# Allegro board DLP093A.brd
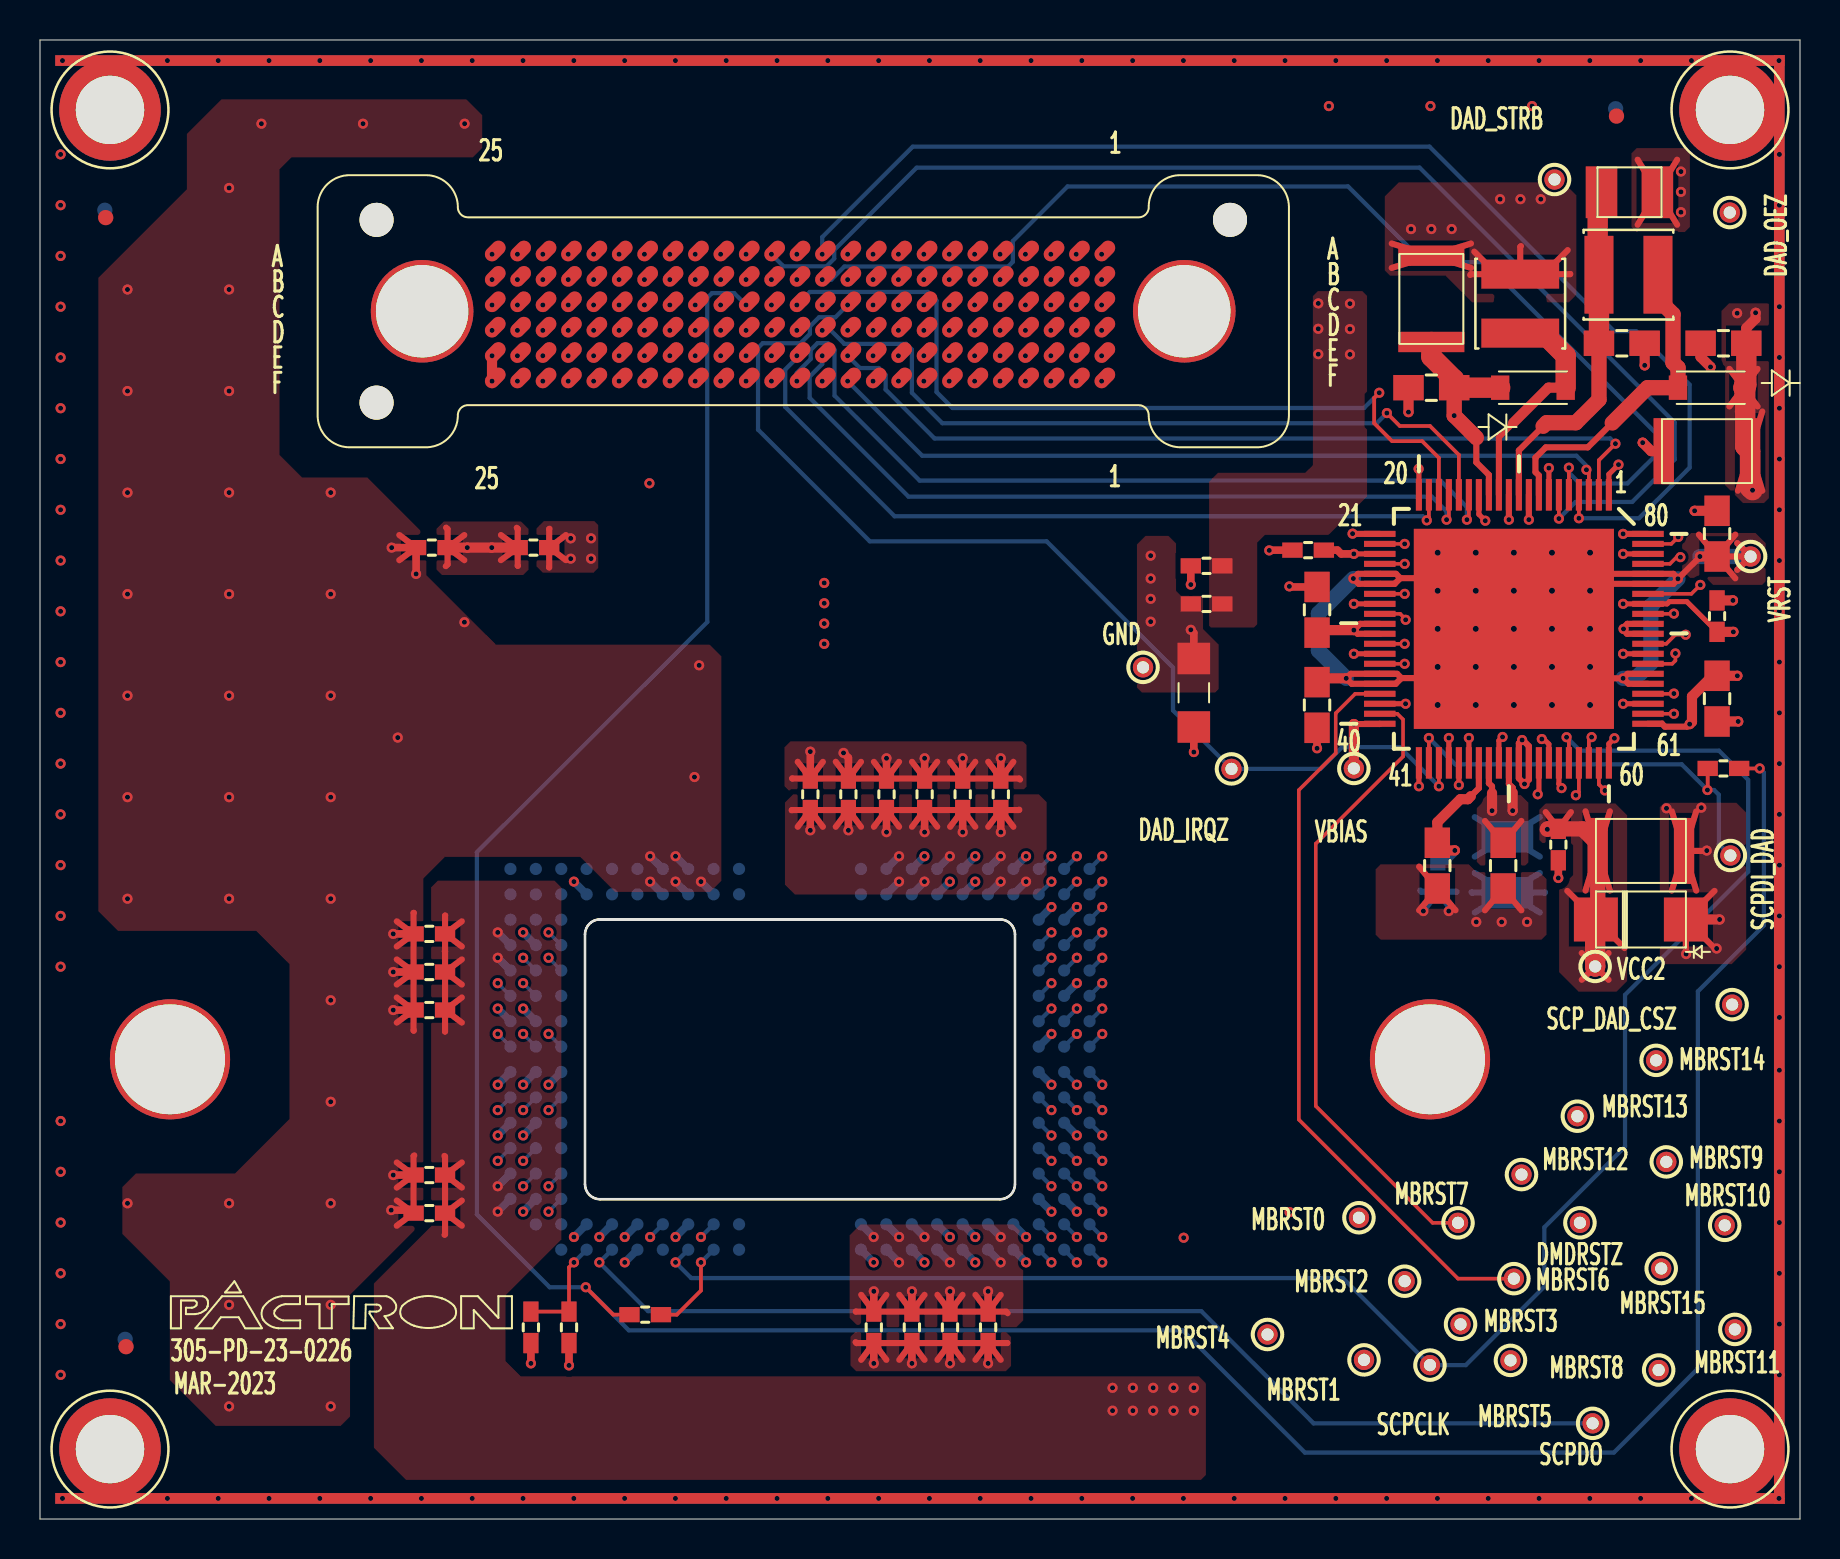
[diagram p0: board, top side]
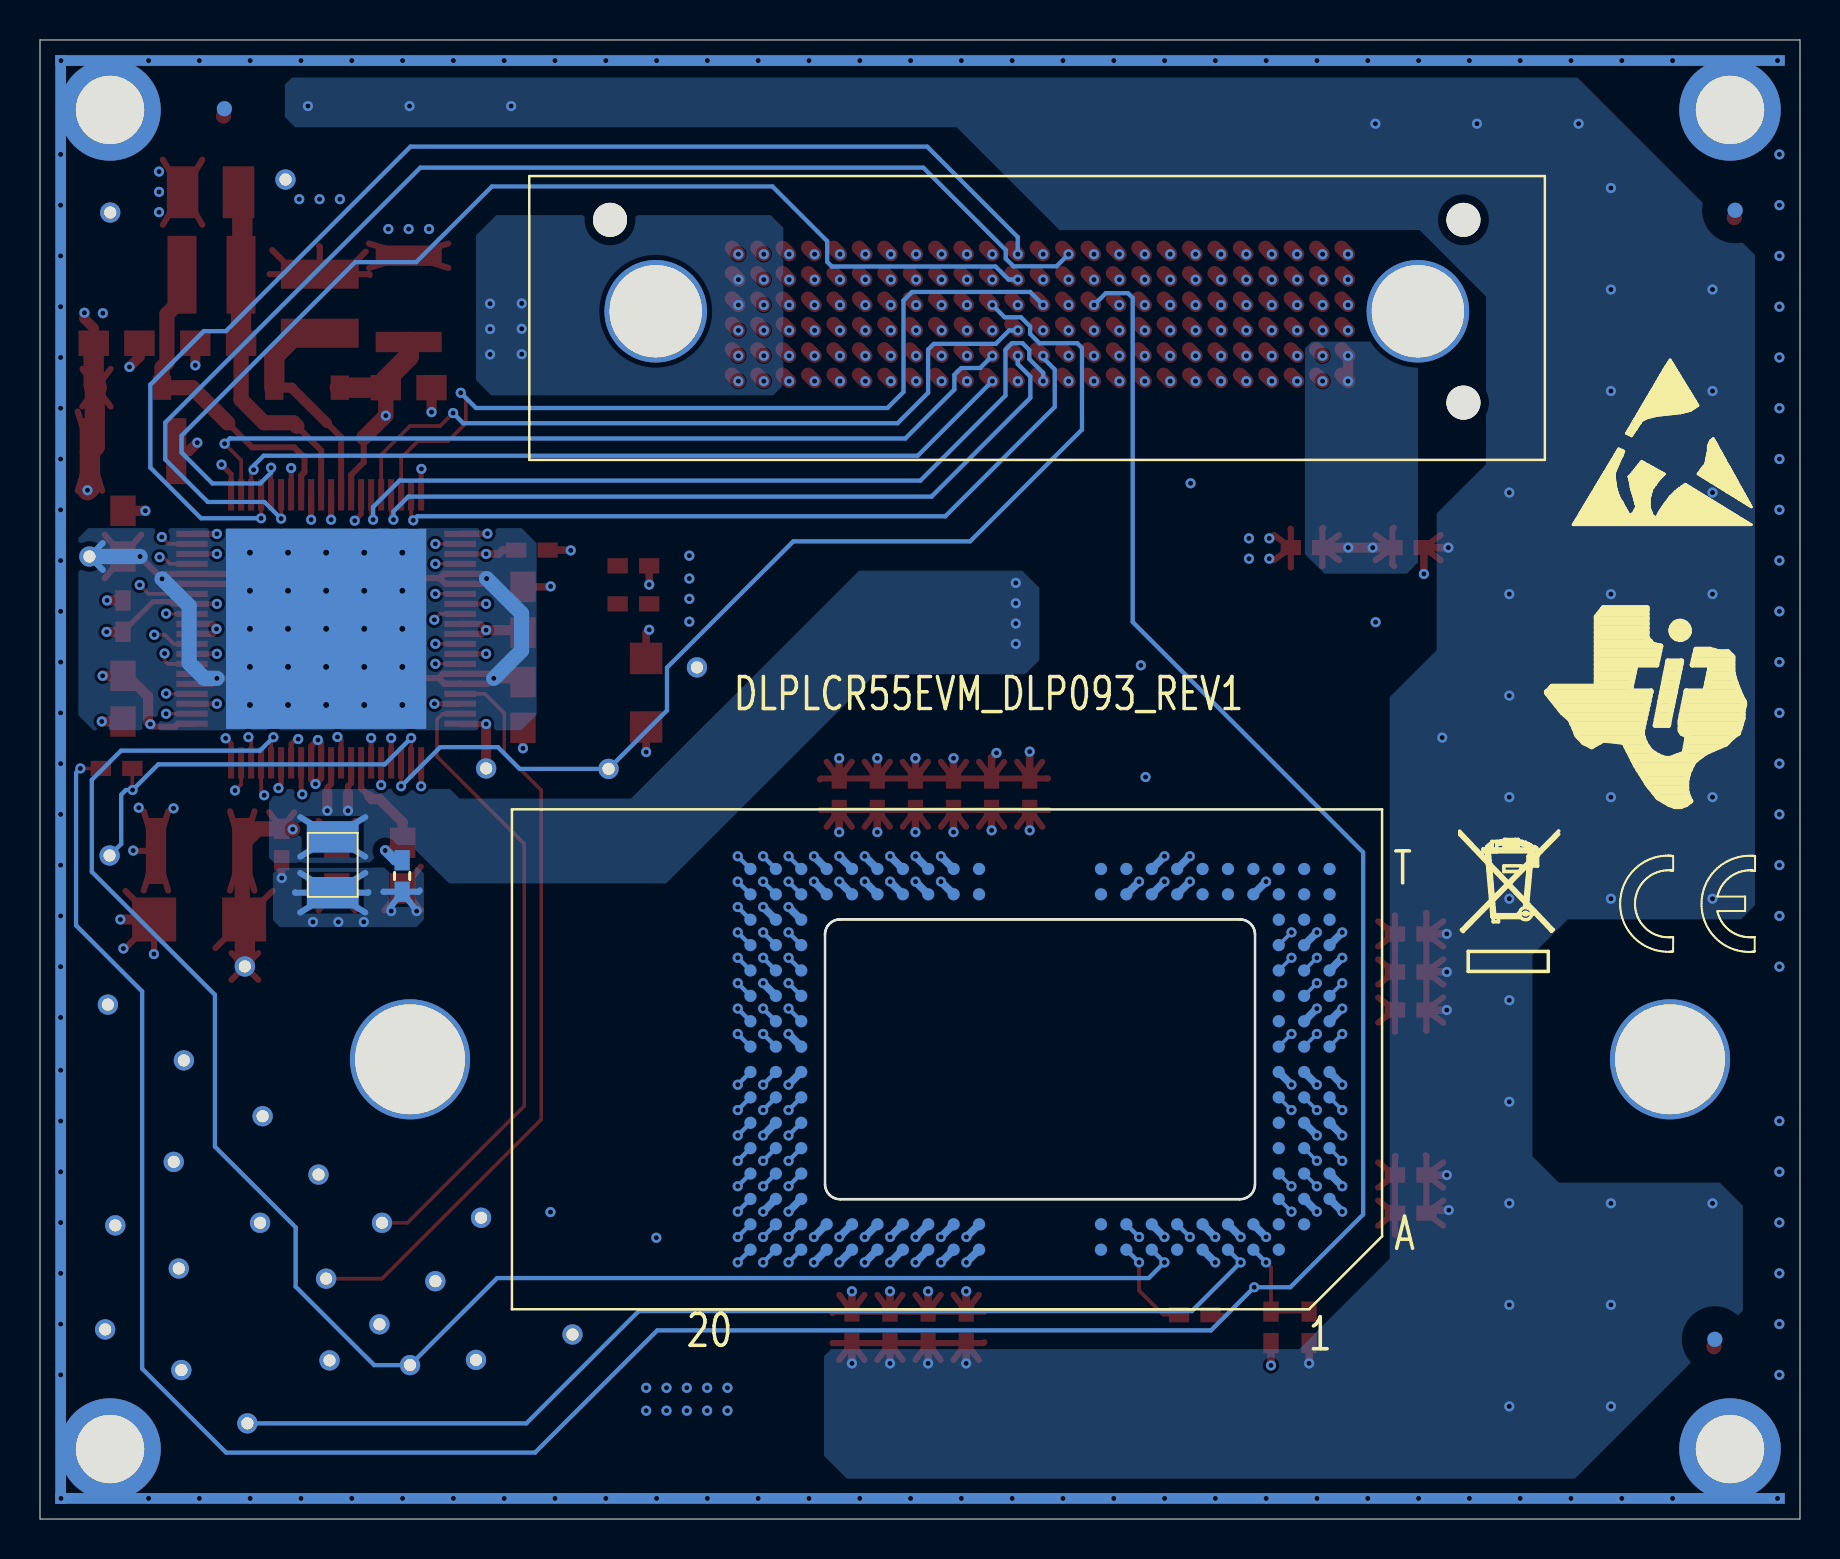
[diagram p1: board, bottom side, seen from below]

Outline 88 x 74 mm; copper layers: TOP, 02_PWR, 03_GND1, 04_SIG1, 05_GND2, 06_SIG2, 07_GND3, BOTTOM. Coordinates in mm from the lower left corner of the outline.
Outline path: 27.25,29.25 arc(27.47,29.78) 28,30 48,30 arc(48.53,29.78) 48.75,29.25 48.75,16.75 arc(48.53,16.22) 48,16 28,16 arc(27.47,16.22) 27.25,16.75 27.25,29.25

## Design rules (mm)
net group C: nets DMDRSTZ SCPCLK SCPDI SCPDO
net group DIFF: nets DCLKAN DCLKAP DCLKBN DCLKBP DDAN5 DDAN9 DDAN11 DDAN13 DDAN15 DDAP5 DDAP9 DDAP11 DDAP13 DDAP15 DDBN3 DDBN5 DDBN7 DDBN9 DDBN13 DDBN15 DDBP3 DDBP5 DDBP7 DDBP9 DDBP13 DDBP15 SCTRLAN SCTRLAP SCTRLBN SCTRLBP
net group MBRST: nets MBRST0 MBRST1 MBRST2 MBRST3 MBRST4 MBRST5 MBRST6 MBRST7 MBRST8 MBRST9 MBRST10 MBRST11 MBRST12 MBRST13 MBRST14 MBRST15
net group POWER_PH: nets DAD_VBIAS_SWL V5REG VBIAS_LHI VRST_SWL

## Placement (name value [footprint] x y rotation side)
C1  0.001uF  [0603AVX]  19.59 48.6 180 top
C2  0.001uF  [0603AVX]  58.33 47.69 180 top
C3  0.1uF  [0603AVX]  38.52 36.26 90 top
C4  0.1uF  [0603AVX]  40.42 36.26 90 top
C5  0.1uF  [0603AVX]  42.33 36.26 90 top
C6  0.1uF  [0603AVX]  44.23 36.26 90 top
C7  0.1uF  [0603AVX]  46.14 36.26 90 top
C8  0.1uF  [0603AVX]  48.04 36.26 90 top
C9  10uF  [1206AVX]  57.69 41.34 270 top
C10  10 uF  [CAP_1210]  79.47 66.38 0 top
C11  0.1uF  [0603AVX]  19.47 29.28 180 top
C12  1uF  [0603AVX]  19.47 27.37 180 top
C13  0.1uF  [0603AVX]  19.47 25.47 180 top
C14  0.1uF  [0603AVX]  63.41 48.48 0 top
C15  4.7 uF  [CAP_1812]  69.57 61.05 270 top
C16  0.1 uF  [CAP_0805]  69.57 56.6 0 top
C17  0.1 uF  [CAP_0805]  79.09 58.83 180 top
C18  0.1 uF  [CAP_0805]  84.17 58.83 0 top
C19  4.7 uF  [CAP_1812]  83.35 53.43 0 top
C20  0.1 uF  [CAP_0805]  83.85 49.3 270 top
C21  0.1uF  [0603AVX]  19.47 17.21 180 top
C22  0.1uF  [0603AVX]  19.47 15.31 180 top
C23  0.1uF  [0603AVX]  41.69 9.59 270 top
C24  0.1uF  [0603AVX]  43.6 9.59 270 top
C25  0.1uF  [0603AVX]  45.5 9.59 270 top
C26  0.1uF  [0603AVX]  47.41 9.59 270 top
C27  0.1 uF  [CAP_0805]  63.85 45.49 270 top
C28  0.1 uF  [CAP_0805]  63.85 40.73 90 top
C29  0.1uF  [0603AVX]  83.85 45.17 270 top
C30  0.1 uF  [CAP_0805]  83.85 41.05 90 top
C31  1uF  [0603AVX]  69.89 32.17 270 bottom
C32  10 uF  [CAP_1210]  73.36 32.73 270 bottom
C33  0.1 uF  [CAP_0805]  69.87 32.69 90 top
C34  0.1 uF  [CAP_0805]  73.16 32.69 90 top
C35  0.1uF  [0603AVX]  75.92 33.74 90 top
C36  4.7 uF  [CAP_1812]  80.04 33.43 180 top
D1  DIODE_SCHOTTKY  [SOD_123]  74.65 56.6 180 top
D2  DIODE_SCHOTTKY  [SOD_123]  83.54 56.6 180 top
D3  9.1V  [DO-214AC]  80.04 30 180 top
J1  DMD_FLEX_CONNECTOR  [CN150CUSTOM_REVB]  53.4 63.6 180 top
L1  68ohms @ 100MHz  [0603AVX]  24.67 48.6 0 top
L2  68ohms @ 100MHz  [0603AVX]  58.33 45.79 0 top
L3  22 uH  [IND_DT1608C]  74.01 60.81 270 top
L4  22 uH  [IND_DT1608C]  79.42 62.25 0 top
MH1  Mounting_Hole  [MOUNTING_HOLE]  3.5 3.5 0 top
MH2  Mounting_Hole  [MOUNTING_HOLE]  84.5 70.5 0 top
MH3  Mounting_Hole  [MOUNTING_HOLE]  3.5 70.5 0 top
MH4  Mounting_Hole  [MOUNTING_HOLE]  84.5 3.5 0 top
NOREF  -  []  28 16 90 top
NOREF#2  -  []  27.25 16.75 0 top
NOREF#3  -  [unnamed#2]  3.29 65.11 0 top
NOREF#4  -  []  -87.55 -119.7 0 top
NOREF#5  -  []  -35.47 -36.19 90 top
NOREF#6  -  []  0 74 0 top
NOREF#7  -  []  119.08 -36.19 90 top
NOREF#8  -  []  -35.47 95.16 90 top
NOREF#9  -  []  0 0 90 top
NOREF#10  -  []  67.48 41.03 0 top
NOREF#11  -  []  -125.33 -140.66 0 top
NOREF#12  -  [unnamed#2]  4.3 8.62 0 top
NOREF#13  -  [unnamed#2]  78.82 70.19 0 top
NOREF#14  -  []  48.62 29.67 0 top
NOREF#15  -  []  19.48 5.03 0 top
NOREF#16  -  []  67.48 5.03 180 bottom
NOREF#17  -  [unnamed#2]  78.78 70.56 180 bottom
NOREF#18  -  [unnamed#2]  3.24 65.48 180 bottom
NOREF#19  -  [unnamed#2]  4.26 8.99 180 bottom
NOREF#20  -  []  21.37 42.13 180 bottom
NOREF#21  -  []  19.48 41.03 180 bottom
NOREF#22  -  [unnamed#3]  38 23 180 bottom
NOREF#23  -  []  45.5 43.4 180 bottom
R1  0  [0603AVX]  24.55 9.59 90 top
R2  0  [0603AVX]  26.45 9.59 270 top
R3  33  [0603AVX]  30.26 10.23 0 top
R4  33  [0603AVX]  84.17 37.55 180 top
TP1  Testpoint  [TP40_24]  55.15 42.61 0 top
TP2  Testpoint  [TP40_24]  65.95 15.07 0 top
TP3  Testpoint  [TP40_24]  66.2 7.96 0 top
TP4  Testpoint  [TP40_24]  68.23 11.9 0 top
TP5  Testpoint  [TP40_24]  71.03 9.74 0 top
TP6  Testpoint  [TP40_24]  61.38 9.23 0 top
TP7  Testpoint  [TP40_24]  73.52 7.94 0 top
TP8  Testpoint  [TP40_24]  73.69 12.03 0 top
TP9  Testpoint  [TP40_24]  70.9 14.82 0 top
TP10  Testpoint  [TP40_24]  80.93 7.45 0 top
TP11  Testpoint  [TP40_24]  81.31 17.87 0 top
TP12  Testpoint  [TP40_24]  84.24 14.69 0 top
TP13  Testpoint  [TP40_24]  84.74 9.49 0 top
TP14  Testpoint  [TP40_24]  74.08 17.23 0 top
TP15  Testpoint  [TP40_24]  76.87 20.15 0 top
TP16  Testpoint  [TP40_24]  80.81 22.95 0 top
TP17  Testpoint  [TP40_24]  81.06 12.53 0 top
TP18  Testpoint  [TP40_24]  69.5 7.7 0 top
TP19  Testpoint  [TP40_24]  77.63 4.79 0 top
TP20  Testpoint  [TP40_24]  84.52 33.2 0 top
TP21  Testpoint  [TP40_24]  84.61 25.74 0 top
TP22  Testpoint  [TP40_24]  59.57 37.53 0 top
TP23  Testpoint  [TP40_24]  75.73 67.02 0 top
TP24  Testpoint  [TP40_24]  84.49 65.37 0 top
TP25  Testpoint  [TP40_24]  77 14.82 0 top
TP26  Testpoint  [TP40_24]  65.69 37.55 0 top
TP27  Testpoint  [TP40_24]  85.53 48.16 0 top
TP28  Testpoint  [TP40_24]  77.76 27.65 0 top
U1  DAD2000  [TQFP80_5MM]  73.69 44.54 180 top
U500  Series 450 DMD  [DMD_S450]  38 23 0 bottom

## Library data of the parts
C1-C9 C11-C31 C33-C36 = CAP NP
C10 C32 = CAP NP: Tolerance: TOL
D1 D2 = DIODE_SCHOTTKY
D3 = DIODE ZENER
J1 = DMD_FLEX_CONNECTOR_1
L1-L4 = INDUCTOR
MH1-MH4 TP1-TP28 = Testpoint
R1-R4 = R
U1 = DAD2000
U500 = Series 450 DMD

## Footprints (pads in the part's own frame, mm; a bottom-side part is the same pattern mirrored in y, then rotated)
0603AVX
  rect 1.016x0.762 smd: 1(-0.787,0) 2(0.787,0)
1206AVX
  rect 1.575x1.626 smd: 1(-1.715,0) 2(1.715,0)
CAP_0805
  rect 1.524x1.27 smd: 1(-1.143,0) 2(1.143,0)
CAP_1210
  rect 1.575x2.591 smd: 1(-1.397,0) 2(1.397,0)
CAP_1812
  rect 1.016x3.302 smd: 1(-2.158,0) 2(2.158,0)
CN150CUSTOM_REVB
  round 1.7 hole 1.7 unplated: (-6.096,-1.397) (36.576,7.747) (36.576,-1.397)
  oval 1.168x0.711 smd rot 45: 1A(0,0) 1B(0,1.27) 1C(0,2.54) 1D(0,3.81) 1E(0,5.08) 1F(0,6.35) 2A(1.27,0) 2B(1.27,1.27) 2C(1.27,2.54) 2D(1.27,3.81) 2E(1.27,5.08) 2F(1.27,6.35) 3A(2.54,0) 3B(2.54,1.27) 3C(2.54,2.54) 3D(2.54,3.81) 3E(2.54,5.08) 3F(2.54,6.35) 4A(3.81,0) 4B(3.81,1.27) 4C(3.81,2.54) 4D(3.81,3.81) 4E(3.81,5.08) 4F(3.81,6.35) 5A(5.08,0) 5B(5.08,1.27) 5C(5.08,2.54) 5D(5.08,3.81) 5E(5.08,5.08) 5F(5.08,6.35) 6A(6.35,0) 6B(6.35,1.27) 6C(6.35,2.54) 6D(6.35,3.81) 6E(6.35,5.08) 6F(6.35,6.35) 7A(7.62,0) 7B(7.62,1.27) 7C(7.62,2.54) 7D(7.62,3.81) 7E(7.62,5.08) 7F(7.62,6.35) 8A(8.89,0) 8B(8.89,1.27) 8C(8.89,2.54) 8D(8.89,3.81) 8E(8.89,5.08) 8F(8.89,6.35) 9A(10.16,0) 9B(10.16,1.27) 9C(10.16,2.54) 9D(10.16,3.81) 9E(10.16,5.08) 9F(10.16,6.35) 10A(11.43,0) 10B(11.43,1.27) 10C(11.43,2.54) 10D(11.43,3.81) 10E(11.43,5.08) 10F(11.43,6.35) 11A(12.7,0) 11B(12.7,1.27) 11C(12.7,2.54) 11D(12.7,3.81) 11E(12.7,5.08) 11F(12.7,6.35) 12A(13.97,0) 12B(13.97,1.27) 12C(13.97,2.54) 12D(13.97,3.81) 12E(13.97,5.08) 12F(13.97,6.35) 13A(15.24,0) 13B(15.24,1.27) 13C(15.24,2.54) 13D(15.24,3.81) 13E(15.24,5.08) 13F(15.24,6.35) 14A(16.51,0) 14B(16.51,1.27) 14C(16.51,2.54) 14D(16.51,3.81) 14E(16.51,5.08) 14F(16.51,6.35) 15A(17.78,0) 15B(17.78,1.27) 15C(17.78,2.54) 15D(17.78,3.81) 15E(17.78,5.08) 15F(17.78,6.35) 16A(19.05,0) 16B(19.05,1.27) 16C(19.05,2.54) 16D(19.05,3.81) 16E(19.05,5.08) 16F(19.05,6.35) 17A(20.32,0) 17B(20.32,1.27) 17C(20.32,2.54) 17D(20.32,3.81) 17E(20.32,5.08) 17F(20.32,6.35) 18A(21.59,0) 18B(21.59,1.27) 18C(21.59,2.54) 18D(21.59,3.81) 18E(21.59,5.08) 18F(21.59,6.35) 19A(22.86,0) 19B(22.86,1.27) 19C(22.86,2.54) 19D(22.86,3.81) 19E(22.86,5.08) 19F(22.86,6.35) 20A(24.13,0) 20B(24.13,1.27) 20C(24.13,2.54) 20D(24.13,3.81) 20E(24.13,5.08) 20F(24.13,6.35) 21A(25.4,0) 21B(25.4,1.27) 21C(25.4,2.54) 21D(25.4,3.81) 21E(25.4,5.08) 21F(25.4,6.35) 22A(26.67,0) 22B(26.67,1.27) 22C(26.67,2.54) 22D(26.67,3.81) 22E(26.67,5.08) 22F(26.67,6.35) 23A(27.94,0) 23B(27.94,1.27) 23C(27.94,2.54) 23D(27.94,3.81) 23E(27.94,5.08) 23F(27.94,6.35) 24A(29.21,0) 24B(29.21,1.27) 24C(29.21,2.54) 24D(29.21,3.81) 24E(29.21,5.08) 24F(29.21,6.35) 25A(30.48,0) 25B(30.48,1.27) 25C(30.48,2.54) 25D(30.48,3.81) 25E(30.48,5.08) 25F(30.48,6.35)
  round 5.131 hole 4.623: MH1(-3.809,3.176) MH2(34.298,3.176)
DMD_S450
  round 0.61 smd: A3(-11.938,9.525) A4(-10.668,9.525) A5(-9.398,9.525) A6(-8.128,9.525) A7(-6.858,9.525) A8(-5.588,9.525) A9(-4.318,9.525) A10(-3.048,9.525) A11(3.048,9.525) A12(4.318,9.525) A13(5.588,9.525) A14(6.858,9.525) A15(8.128,9.525) A16(9.398,9.525) A17(10.668,9.525) A18(11.938,9.525) A19(13.208,9.525) A20(14.478,9.525) B2(-13.208,8.255) B3(-11.938,8.255) B4(-10.668,8.255) B5(-9.398,8.255) B6(-8.128,8.255) B7(-6.858,8.255) B8(-5.588,8.255) B9(-4.318,8.255) B10(-3.048,8.255) B11(3.048,8.255) B12(4.318,8.255) B13(5.588,8.255) B14(6.858,8.255) B15(8.128,8.255) B16(9.398,8.255) B17(10.668,8.255) B18(11.938,8.255) B19(13.208,8.255) B20(14.478,8.255) C1(-14.478,6.985) C2(-13.208,6.985) C3(-11.938,6.985) C18(11.938,6.985) C19(13.208,6.985) C20(14.478,6.985) D1(-14.478,5.715) D2(-13.208,5.715) D3(-11.938,5.715) D18(11.938,5.715) D19(13.208,5.715) D20(14.478,5.715) E1(-14.478,4.445) E2(-13.208,4.445) E3(-11.938,4.445) E18(11.938,4.445) E19(13.208,4.445) E20(14.478,4.445) F1(-14.478,3.175) F2(-13.208,3.175) F3(-11.938,3.175) F18(11.938,3.175) F19(13.208,3.175) F20(14.478,3.175) G1(-14.478,1.905) G2(-13.208,1.905) G3(-11.938,1.905) G18(11.938,1.905) G19(13.208,1.905) G20(14.478,1.905) H1(-14.478,0.635) H2(-13.208,0.635) H3(-11.938,0.635) H18(11.938,0.635) H19(13.208,0.635) H20(14.478,0.635) J1(-14.478,-0.635) J2(-13.208,-0.635) J3(-11.938,-0.635) J18(11.938,-0.635) J19(13.208,-0.635) J20(14.478,-0.635) K1(-14.478,-1.905) K2(-13.208,-1.905) K3(-11.938,-1.905) K18(11.938,-1.905) K19(13.208,-1.905) K20(14.478,-1.905) L1(-14.478,-3.175) L2(-13.208,-3.175) L3(-11.938,-3.175) L18(11.938,-3.175) L19(13.208,-3.175) L20(14.478,-3.175) M1(-14.478,-4.445) M2(-13.208,-4.445) M3(-11.938,-4.445) M18(11.938,-4.445) M19(13.208,-4.445) M20(14.478,-4.445) N1(-14.478,-5.715) N2(-13.208,-5.715) N3(-11.938,-5.715) N18(11.938,-5.715) N19(13.208,-5.715) N20(14.478,-5.715) P1(-14.478,-6.985) P2(-13.208,-6.985) P3(-11.938,-6.985) P18(11.938,-6.985) P19(13.208,-6.985) P20(14.478,-6.985) R1(-14.478,-8.255) R2(-13.208,-8.255) R3(-11.938,-8.255) R4(-10.668,-8.255) R5(-9.398,-8.255) R6(-8.128,-8.255) R7(-6.858,-8.255) R8(-5.588,-8.255) R9(-4.318,-8.255) R10(-3.048,-8.255) R11(3.048,-8.255) R12(4.318,-8.255) R13(5.588,-8.255) R14(6.858,-8.255) R15(8.128,-8.255) R16(9.398,-8.255) R17(10.668,-8.255) R18(11.938,-8.255) R19(13.208,-8.255) R20(14.478,-8.255) T1(-14.478,-9.525) T2(-13.208,-9.525) T3(-11.938,-9.525) T4(-10.668,-9.525) T5(-9.398,-9.525) T6(-8.128,-9.525) T7(-6.858,-9.525) T8(-5.588,-9.525) T9(-4.318,-9.525) T10(-3.048,-9.525) T11(3.048,-9.525) T12(4.318,-9.525) T13(5.588,-9.525) T14(6.858,-9.525) T15(8.128,-9.525) T16(9.398,-9.525) T17(10.668,-9.525) T18(11.938,-9.525) T19(13.208,-9.525) T20(14.478,-9.525)
DO-214AC
  rect 2.2x2.2 smd: 1(2.25,0) 2(-2.25,0)
IND_DT1608C
  rect 1.45x3.89 smd: 1(-1.475,0) 2(1.475,0)
MOUNTING_HOLE
  round 5.08 hole 3.42: 1(0,0)
SOD_123
  rect 0.914x1.219 smd: 1(-1.638,0) 2(1.638,0)
TP40_24
  round 1.016 hole 0.61: 1(0,0)
TQFP80_5MM
  rect 0.305x1.575 smd: 1(-4.75,-6.706) 2(-4.249,-6.706) 3(-3.749,-6.706) 4(-3.251,-6.706) 5(-2.751,-6.706) 6(-2.25,-6.706) 7(-1.75,-6.706) 8(-1.25,-6.706) 9(-0.749,-6.706) 10(-0.249,-6.706) 11(0.249,-6.706) 12(0.749,-6.706) 13(1.25,-6.706) 14(1.75,-6.706) 15(2.25,-6.706) 16(2.751,-6.706) 17(3.251,-6.706) 18(3.749,-6.706) 19(4.249,-6.706) 20(4.75,-6.706) 41(4.75,6.706) 42(4.249,6.706) 43(3.749,6.706) 44(3.251,6.706) 45(2.751,6.706) 46(2.25,6.706) 47(1.75,6.706) 48(1.25,6.706) 49(0.749,6.706) 50(0.249,6.706) 51(-0.249,6.706) 52(-0.749,6.706) 53(-1.25,6.706) 54(-1.75,6.706) 55(-2.25,6.706) 56(-2.751,6.706) 57(-3.251,6.706) 58(-3.749,6.706) 59(-4.249,6.706) 60(-4.75,6.706)
  rect 1.575x0.305 smd: 21(6.706,-4.75) 22(6.706,-4.249) 23(6.706,-3.749) 24(6.706,-3.251) 25(6.706,-2.751) 26(6.706,-2.25) 27(6.706,-1.75) 28(6.706,-1.25) 29(6.706,-0.749) 30(6.706,-0.249) 31(6.706,0.249) 32(6.706,0.749) 33(6.706,1.25) 34(6.706,1.75) 35(6.706,2.25) 36(6.706,2.751) 37(6.706,3.251) 38(6.706,3.749) 39(6.706,4.249) 40(6.706,4.75) 61(-6.706,4.75) 62(-6.706,4.249) 63(-6.706,3.749) 64(-6.706,3.251) 65(-6.706,2.751) 66(-6.706,2.25) 67(-6.706,1.75) 68(-6.706,1.25) 69(-6.706,0.749) 70(-6.706,0.249) 71(-6.706,-0.249) 72(-6.706,-0.749) 73(-6.706,-1.25) 74(-6.706,-1.75) 75(-6.706,-2.25) 76(-6.706,-2.751) 77(-6.706,-3.251) 78(-6.706,-3.749) 79(-6.706,-4.249) 80(-6.706,-4.75)
unnamed#2
  round 0.762 smd: (0,0)
unnamed#3
  round 6.008 hole 5.5 unplated: (-31.5,0) (31.5,0)

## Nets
GND: C1.2 C2.2 C3.2 C4.2 C5.2 C6.2 C7.2 C8.2 C9.2 C10.2 C11.2 C12.2 C13.2 C14.1 C15.1 C16.1 C17.1 C18.1 C19.1 C20.1 C21.2 C22.2 C23.2 C24.2 C25.2 C26.2 C27.1 C28.1 C29.1 C30.1 C31.2 C32.2 C33.1 C34.1 C35.1 C36.1 D3.2(ANODE) J1.1A J1.1D J1.2C J1.2F J1.3A J1.3D J1.4C J1.4F J1.5A J1.5D J1.6C J1.6F J1.7A J1.7D J1.8C J1.8F J1.9A J1.9D J1.10C J1.10F J1.11A J1.11D J1.12C J1.12F J1.13D J1.14C J1.14F J1.15A J1.15D J1.16C J1.16F J1.17A J1.17D J1.18C J1.18F J1.19A J1.19D J1.20C J1.20F J1.21A J1.21D J1.22C J1.22F J1.23A J1.23D J1.24C J1.24F J1.25A J1.25D J1.MH1 J1.MH2 L3.1 MH1.1 MH2.1 MH3.1 MH4.1 R1.1 TP1.1 U1.1(GND_1) U1.7(GND_7) U1.14(GND_14) U1.20(GND_20) U1.41(GND_41) U1.44(DEV_ID0) U1.45(DEV_ID1) U1.46(GND_46) U1.53(GND_53) U1.54(VCC/NC) U1.55(GND_55) U1.60(GND_60) U500.A6(GND#A6) U500.A11(GND#A11) U500.A13(GND#A13) U500.A15(GND#A15) U500.A17(GND#A17) U500.B4(GND#B4) U500.B5(GND#B5) U500.B6(RESERVED_STM) U500.B8(GND#B8) U500.B14(GND#B14) U500.B15(GND#B15) U500.B17(GND#B17) U500.C2(GND#C2) U500.C18(GND#C18) U500.C19(GND#C19) U500.F1(GND#F1) U500.F2(GND#F2) U500.F19(GND#F19) U500.H1(GND#H1) U500.H2(GND#H2) U500.H3(GND#H3) U500.H18(GND#H18) U500.J18(GND#J18) U500.K1(GND#K1) U500.K2(GND#K2) U500.L19(GND#L19) U500.N2(GND#N2) U500.P18(GND#P18) U500.P19(GND#P19) U500.R4(GND#R4) U500.R7(RESERVED_FC) U500.R8(RESERVED_FD) U500.R9(GND#R9) U500.R14(GND#R14) U500.R15(GND#R15) U500.T7(GND#T7) U500.T8(RESERVED_PFE) U500.T13(GND#T13) U500.T15(GND#T15) U500.T17(GND#T17)
P12V: C32.1 C34.2 J1.10D J1.10E J1.11B U1.11(V12_1) U1.48(V12_2) U1.50(V12_3)
V5REG: C31.1 C33.2 U1.47(V5REG)
V12_SWL-NC: U1.51(V12_SWL-NC#51) U1.52(V12_SWL-NC#52)
VCC: C3.1 C4.1 C5.1 C6.1 C7.1 C8.1 C9.1 C23.1 C24.1 C25.1 C26.1 L1.2 L2.1 R2.2 U500.A12(VCCI#A12) U500.A14(VCCI#A14) U500.A16(VCCI#A16) U500.B11(VCC#B11) U500.B12(VCC#B12) U500.B13(VCC#B13) U500.B16(VCC#B16) U500.R12(VCC#R12) U500.R13(VCC#R13) U500.R16(VCC#R16) U500.R17(VCC#R17) U500.T12(VCCI#T12) U500.T14(VCCI#T14) U500.T16(VCCI#T16)
VCC2: C11.1 C12.1 C13.1 C14.2 C21.1 C22.1 C29.2 C35.2 C36.2 D3.1(CATHODE) TP28.1 U1.23(VOFFSET_RAIL0) U1.28(VOFFSET_RAIL1) U1.33(VOFFSET_RAIL2) U1.38(VOFFSET_RAIL3) U1.49(VOFFSET) U1.63(VOFFSET_RAIL4) U1.68(VOFFSET_RAIL5) U1.73(VOFFSET_RAIL6) U1.78(VOFFSET_RAIL7) U500.C1(VCC2#C1) U500.D1(VCC2#D1) U500.M1(VCC2#M1) U500.N1(VCC2#N1)
3P3V: C2.1 J1.1B J1.1C L2.2
13A: J1.13A
13B: J1.13B
DAD_ADDR_0: J1.13E U1.19(A0)
DAD_ADDR_1: J1.13C U1.18(A1)
DAD_ADDR_2: J1.12E U1.17(A2)
DAD_ADDR_3: J1.12D U1.16(A3)
DAD_IRQZ: J1.11C TP22.1 U1.43(IRQZ)
DAD_MODE_0: J1.11F U1.3(MODE0)
DAD_MODE_1: J1.11E U1.2(MODE1)
DAD_OEZ: J1.14A TP24.1 U1.6(OEZ)
DAD_SEL_0: J1.12B U1.5(SEL0)
DAD_SEL_1: J1.12A U1.4(SEL1)
DAD_STRB: J1.13F TP23.1 U1.15(STROBE)
DAD_VBIAS_SWL: D2.2(A) L4.2 U1.8(VBIAS_SWL)
DCLKAN: J1.21E U500.D19(DCLKA-)
DCLKAP: J1.21F U500.E19(DCLKA+)
DCLKBN: J1.5E U500.N19(DCLKB-)
DCLKBP: J1.5F U500.M19(DCLKB+)
DDAN1: J1.17E U500.G20(DDA1-)
DDAN3: J1.18D U500.H19(DDA3-)
DDAN5: J1.19E U500.F18(DDA5-)
DDAN7: J1.20D U500.E18(DDA7-)
DDAN9: J1.22D U500.C20(DDA9-)
DDAN11: J1.23E U500.B18(DDA11-)
DDAN13: J1.24D U500.A20(DDA13-)
DDAN15: J1.25B U500.B19(DDA15-)
DDAP1: J1.17F U500.H20(DDA1+)
DDAP3: J1.18E U500.G19(DDA3+)
DDAP5: J1.19F U500.G18(DDA5+)
DDAP7: J1.20E U500.D18(DDA7+)
DDAP9: J1.22E U500.D20(DDA9+)
DDAP11: J1.23F U500.A18(DDA11+)
DDAP13: J1.24E U500.B20(DDA13+)
DDAP15: J1.25C U500.A19(DDA15+)
DDBN1: J1.9E U500.K20(DDB1-)
DDBN3: J1.8D U500.J19(DDB3-)
DDBN5: J1.7E U500.L18(DDB5-)
DDBN7: J1.6D U500.M18(DDB7-)
DDBN9: J1.4D U500.P20(DDB9-)
DDBN11: J1.3E U500.R18(DDB11-)
DDBN13: J1.2D U500.T20(DDB13-)
DDBN15: J1.1E U500.R19(DDB15-)
DDBP1: J1.9F U500.J20(DDB1+)
DDBP3: J1.8E U500.K19(DDB3+)
DDBP5: J1.7F U500.K18(DDB5+)
DDBP7: J1.6E U500.N18(DDB7+)
DDBP9: J1.4E U500.N20(DDB9+)
DDBP11: J1.3F U500.T18(DDB11+)
DDBP13: J1.2E U500.R20(DDB13+)
DDBP15: J1.1F U500.T19(DDB15+)
DMDRSTZ: J1.15B TP25.1 U1.59(RESETZ) U500.B9(PWRDNZ)
MBRST0: TP2.1 U1.22(OUT00) U500.C3(MBRST00)
MBRST1: TP3.1 U1.24(OUT01) U500.D2(MBRST01)
MBRST2: TP4.1 U1.27(OUT02) U500.D3(MBRST02)
MBRST3: TP5.1 U1.29(OUT03) U500.E2(MBRST03)
MBRST4: TP6.1 U1.32(OUT04) U500.G3(MBRST04)
MBRST5: TP7.1 U1.34(OUT05) U500.E1(MBRST05)
MBRST6: TP8.1 U1.37(OUT06) U500.G2(MBRST06)
MBRST7: TP9.1 U1.39(OUT07) U500.G1(MBRST07)
MBRST8: TP10.1 U1.62(OUT08) U500.N3(MBRST08)
MBRST9: TP11.1 U1.64(OUT09) U500.M2(MBRST09)
MBRST10: TP12.1 U1.67(OUT10) U500.M3(MBRST10)
MBRST11: TP13.1 U1.69(OUT11) U500.L2(MBRST11)
MBRST12: TP14.1 U1.72(OUT12) U500.J3(MBRST12)
MBRST13: TP15.1 U1.74(OUT13) U500.L1(MBRST13)
MBRST14: TP16.1 U1.77(OUT14) U500.J2(MBRST14)
MBRST15: TP17.1 U1.79(OUT15) U500.J1(MBRST15)
MODE_A: R1.2 R2.1 U500.A4(MODE_A)
SCP_DAD_CSZ: J1.14E TP21.1 U1.58(SCPEN/)
SCPCLK: J1.16D TP18.1 U1.56(SCPCK) U500.A8(SCPCLK)
SCPDI: J1.15C R3.1 R4.1
SCPDI_DAD: R4.2 TP20.1 U1.42(SCPDO)
SCPDI_RS: R3.2 U500.A9(SCPDO)
SCPDO: J1.16E TP19.1 U1.57(SCPDI) U500.A5(SCPDI)
SCPENZ: J1.15E U500.B7(SCPENZ)
SCTRLAN: J1.20A U500.F20(SCTRLA-)
SCTRLAP: J1.20B U500.E20(SCTRLA+)
SCTRLBN: J1.6A U500.L20(SCTRLB-)
SCTRLBP: J1.6B U500.M20(SCTRLB+)
VBIAS: C18.2 C19.2 C27.2 C30.2 D2.1(C) TP26.1 U1.9(VBIAS) U1.21(VBIAS_RAIL0) U1.30(VBIAS_RAIL1) U1.31(VBIAS_RAIL2) U1.40(VBIAS_RAIL3) U1.61(VBIAS_RAIL4) U1.70(VBIAS_RAIL5) U1.71(VBIAS_RAIL6) U1.80(VBIAS_RAIL7)
VBIAS_LHI: C10.1 C17.2 L4.1 U1.10(VBIAS_LHI)
VRST: C15.2 C16.2 C20.2 C28.2 D1.2(A) TP27.1 U1.13(VRESET) U1.25(VRESET_RAIL0) U1.26(VRESET_RAIL1) U1.35(VRESET_RAIL2) U1.36(VRESET_RAIL3) U1.65(VRESET_RAIL4) U1.66(VRESET_RAIL5) U1.75(VRESET_RAIL6) U1.76(VRESET_RAIL7)
VRST_SWL: D1.1(C) L3.2 U1.12(VRESET_SWL)
N28103: C1.1 J1.25E J1.25F L1.1

Pads without a net: J1 2A 2B 3B 3C 4A 4B 5B 5C 7B 7C 8A 8B 9B 9C 10A 10B 14B 14D 15F 16A 16B 17B 17C 18A 18B 19B 19C 21B 21C 22A 22B 23B 23C 24A 24B; U500 A3 A7 A10 B2 B3 B10 E3 F3 K3 L3 P1 P2 P3 R1 R2 R3 R5 R6 R10 R11 T1 T2 T3 T4 T5 T6 T9 T10 T11

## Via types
v1: diameter 0.508, hole 0.254, TOP to BOTTOM, 598 vias
v2: diameter 0.61, hole 0.305, TOP to BOTTOM, 25 vias

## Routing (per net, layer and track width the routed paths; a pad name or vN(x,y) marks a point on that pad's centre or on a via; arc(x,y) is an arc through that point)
GND: length 451.1
  TOP w0.254: v1(76.08,36.57) 76.08,36.64 75.94,36.77 U1.55 ; v1(72.26,49.95) 71.94,50.27 U1.14 ; U1.60 78.44,38.79 v1(78.72,39.06) ; U1.20 68.94,52.53 v1(68.93,52.54) ; U1.53 74.94,36.32 v1(74.89,36.26) ; U1.44 v1(70.44,39.08) ; U1.41 v1(68.94,36.66) ; U1.1 78.44,52.27 v1(78.93,52.76) ; U1.54 75.44,38.77 75.19,39.02 v1(75.09,39.02) ; U1.45 v1(70.94,36.72) ; U1.7 v1(75.44,52.58) ; U1.46 v1(71.44,39.08)
  TOP w0.305: 37.89,37.89 C3.2 ; C3.2 37.61,37.05 37.61,37.06 ; C3.2 C4.2 ; C3.2 39.14,37.89 ; C24.2 44.22,7.96 ; C24.2 C23.2 ; C24.2 C25.2 ; C24.2 42.97,7.96 ; C13.2 18.68,24.44 18.69,24.43 ; C13.2 C12.2 ; C13.2 17.84,26.09 ; C13.2 17.84,24.84 ; C8.2 48.95,37.05 49,37 ; C8.2 48.67,37.89 ; C8.2 C7.2 ; C8.2 47.41,37.89 ; 39.79,37.89 C4.2 ; C4.2 C5.2 ; C4.2 41.05,37.89 ; 79.88,68.01 C10.2 ; C10.2 79.88,64.76 ; C10.2 81.86,68.01 ; C10.2 81.86,64.76 ; 81.59,31.44 C36.1 ; C36.1 81.59,35.41 ; C36.1 82.81,35.41 ; C36.1 82.81,31.44 ; C36.1 83.32,33.43 v1(83.34,33.44) ; C6.2 C7.2 ; C6.2 44.86,37.89 ; C6.2 C5.2 ; C6.2 43.6,37.89 ; C7.2 46.76,37.89 ; C7.2 45.51,37.89 ; 17.84,28.65 C11.2 ; C11.2 18.68,30.32 18.69,30.33 ; C11.2 17.84,29.9 ; C11.2 C12.2 ; C23.2 40.82,8.8 40.78,8.85 ; C23.2 41.06,7.96 ; C23.2 42.32,7.96 ; 18.71,18.2 18.68,18.16 C21.2 ; C25.2 46.13,7.96 ; C25.2 C26.2 ; C25.2 44.87,7.96 ; D3.2 83.72,28.57 ; D3.2 83.72,31.43 ; D3.2 82.29,28.28 v1(82.3,28.27) ; L3.1 74.01,63.65 74.05,63.69 ; L3.1 75.18,62.28 ; L3.1 72.84,62.28 ; C12.2 17.84,28 ; C12.2 17.84,26.74 ; 74.07,30.46 C34.1 72.25,30.46 ; C26.2 48.03,7.96 ; C26.2 48.36,8.8 48.37,8.81 ; C26.2 46.78,7.96 ; 41.7,37.89 C5.2 ; C5.2 42.95,37.89 ; 75.18,62.28 76.5,62.28 76.51,62.29 ; 75.18,62.28 76.39,63.49 ; 17.84,14.68 C22.2 ; C22.2 17.84,15.93 ; C22.2 C21.2 ; 17.84,16.58 C21.2 ; C21.2 17.84,17.84 ; 72.84,62.28 71.55,62.28 71.51,62.24 ; 72.84,62.28 71.71,63.41 ; 17.97,47.97 C1.2 17.97,49.23 ; 67.58,63.82 C15.1 ; C15.1 71.55,63.82 ; C15.1 71.55,62.6 ; C15.1 67.58,62.6 ; 68.96,30.46 C33.1 ; C33.1 68.96,32.64 ; C33.1 70.78,30.46
  TOP w0.381: v1(17.58,48.6) C1.2 v1(18.81,47.28) ; v1(17.66,27.37) C12.2 ; v1(17.66,17.21) C21.2 ; v1(47.41,7.79) C26.2 ; v1(17.66,25.47) C13.2 ; C35.1 v1(75.92,32.07) ; C2.2 v1(57.54,46.75) ; C22.2 18.53,15.46 v1(17.56,15.46) ; C27.1 62.5,46.63 v1(62.47,46.66) ; v1(17.66,29.28) C11.2 ; C4.2 40.42,38.09 v1(40.18,38.33) ; v1(42.33,38.06) C5.2 ; v1(57.69,38.37) C9.2 ; v1(44.23,38.06) C6.2 ; v1(46.14,38.06) C7.2 ; v1(61.46,48.46) 61.48,48.48 C14.1 ; v1(41.69,7.79) C23.2 ; C3.2 v1(38.52,38.4) ; v1(45.5,7.79) C25.2 ; v1(48.04,38.06) C8.2 ; C28.1 v1(63.85,38.56) ; v1(43.6,7.79) C24.2 ; v1(24.55,7.79) R1.1
  TOP w0.508: D3.2 v1(83.98,30) ; v1(83.53,57.64) 83.03,58.14 C18.1 ; C20.1 v1(82.73,50.44) ; C19.1 80.56,53.43 v1(80.14,53.85) ; C17.1 v1(80.23,57.72) ; C30.1 v1(84.91,39.9) ; v1(68.42,55.38) C16.1 ; C29.1 v1(84.65,45.96)
  03_GND1 w0.305: 16.98,58.3 J1.MH2 ; J1.MH2 21.23,58.3 ; J1.MH2 16.98,62.55 ; J1.MH2 21.23,62.55 ; 1.39,72.61 MH3.1 ; MH3.1 5.61,68.39 ; MH3.1 5.61,72.61 ; MH3.1 1.39,68.39 ; 82.39,1.39 MH4.1 ; MH4.1 82.39,5.61 ; MH4.1 86.61,5.61 ; MH4.1 86.61,1.39 ; MH2.1 86.61,68.39 ; MH2.1 82.39,72.61 ; MH2.1 82.39,68.39 ; MH2.1 86.61,72.61 ; 55.09,62.55 J1.MH1 ; J1.MH1 55.09,58.3 ; J1.MH1 59.34,62.55 ; J1.MH1 59.34,58.3 ; 1.39,5.61 MH1.1 ; MH1.1 1.39,1.39 ; MH1.1 5.61,1.39 ; MH1.1 5.61,5.61 ; TP1.1 55.82,43.28 ; TP1.1 55.82,41.94 ; TP1.1 54.48,43.28 ; TP1.1 54.48,41.94
  04_SIG1 w0.305: J1.MH2 21.23,58.3 ; J1.MH2 21.23,62.55 ; J1.MH2 16.98,62.55 ; J1.MH2 16.98,58.3
  05_GND2 w0.305: 16.98,58.3 J1.MH2 ; J1.MH2 21.23,58.3 ; J1.MH2 21.23,62.55 ; J1.MH2 16.98,62.55 ; 1.39,72.61 MH3.1 ; MH3.1 5.61,68.39 ; MH3.1 1.39,68.39 ; MH3.1 5.61,72.61 ; 55.09,62.55 J1.MH1 ; J1.MH1 59.34,62.55 ; J1.MH1 55.09,58.3 ; J1.MH1 59.34,58.3 ; TP1.1 55.82,41.94 ; TP1.1 54.48,41.94 ; TP1.1 54.48,43.28 ; TP1.1 55.82,43.28 ; MH2.1 86.61,68.39 ; MH2.1 82.39,68.39 ; MH2.1 86.61,72.61 ; MH2.1 82.39,72.61 ; MH4.1 86.61,5.61 ; MH4.1 86.61,1.39 ; MH4.1 82.39,1.39 ; MH4.1 82.39,5.61 ; MH1.1 5.61,5.61 ; MH1.1 1.39,5.61 ; MH1.1 5.61,1.39 ; MH1.1 1.39,1.39
  07_GND3 w0.305: MH1.1 5.61,1.39 ; MH1.1 1.39,1.39 ; MH1.1 1.39,5.61 ; MH1.1 5.61,5.61 ; MH4.1 86.61,5.61 ; MH4.1 82.39,5.61 ; MH4.1 86.61,1.39 ; MH4.1 82.39,1.39 ; 55.09,58.3 J1.MH1 ; J1.MH1 59.34,58.3 ; J1.MH1 59.34,62.55 ; J1.MH1 55.09,62.55 ; MH3.1 5.61,72.61 ; MH3.1 1.39,68.39 ; MH3.1 1.39,72.61 ; MH3.1 5.61,68.39 ; 82.39,68.39 MH2.1 ; MH2.1 82.39,72.61 ; MH2.1 86.61,72.61 ; MH2.1 86.61,68.39 ; 16.98,62.55 J1.MH2 ; J1.MH2 16.98,58.3 ; J1.MH2 21.23,62.55 ; J1.MH2 21.23,58.3 ; TP1.1 55.82,41.94 ; TP1.1 54.48,43.28 ; TP1.1 54.48,41.94 ; TP1.1 55.82,43.28
  BOTTOM w0.305: 69.26,30.55 C31.2 ; C31.2 70.52,30.55 ; C31.2 70.82,31.38 70.83,31.38 ; C31.2 69.07,31.38 69.01,31.45 ; 71.74,32.32 C32.2 ; C32.2 74.99,32.32 ; C32.2 75.23,31.34 75.25,31.36 ; C32.2 71.74,30.35 ; C32.2 71.61,31.34 71.58,31.37 ; C32.2 74.99,30.35
  BOTTOM w0.381: v1(44.22,12.84) U500.A13 ; v1(25.43,21.73) U500.H3 ; v1(31.78,33.16) U500.T8 ; v1(31.78,31.89) U500.R8 ; v1(27.97,14.11) U500.B5 ; v1(50.57,21.73) U500.H18 ; v1(33.05,31.89) U500.R9 ; v1(24.16,25.54) U500.K2 ; v1(22.89,21.73) U500.H1 ; v1(49.3,14.11) U500.B17 ; v1(51.84,26.81) U500.L19 ; v1(46.76,31.89) U500.R15 ; v1(30.51,31.89) U500.R7 ; v1(46.76,33.16) U500.T15 ; v1(29.24,14.11) U500.B6 ; v1(51.84,19.19) U500.F19 ; v1(46.76,14.11) U500.B15 ; v1(24.16,29.35) U500.N2 ; v1(26.7,14.11) U500.B4 ; v1(46.76,12.84) U500.A15 ; v1(24.16,15.38) U500.C2 ; v1(45.49,31.89) U500.R14 ; v1(49.3,12.84) U500.A17 ; v1(50.57,15.38) U500.C18 ; v1(31.78,14.11) U500.B8 ; v1(22.89,19.19) U500.F1 ; v1(26.7,31.89) U500.R4 ; v1(49.3,33.16) U500.T17 ; v1(45.49,14.11) U500.B14 ; v1(44.22,33.16) U500.T13 ; v1(51.84,30.62) U500.P19 ; v1(30.51,33.16) U500.T7 ; v1(41.68,12.84) U500.A11 ; v1(24.16,21.73) U500.H2 ; v1(50.57,30.62) U500.P18 ; v1(29.24,12.84) U500.A6 ; v1(51.84,15.38) U500.C19 ; v1(22.89,25.54) U500.K1 ; v1(24.16,19.19) U500.F2 ; v1(50.57,24.27) U500.J18
  vias: v1(1.03,68.27) v1(1.03,65.73) v1(1.03,63.19) v1(1.03,60.65) v1(1.03,58.11) v1(1.03,55.57) v1(1.03,53.03) v1(1.03,50.49) v1(1.03,47.95) v1(1.03,45.41) v1(1.03,42.87) v1(1.03,40.33) v1(1.03,37.79) v1(1.03,35.25) v1(1.03,32.71) v1(1.03,30.17) v1(1.03,27.63) v1(1.12,72.97) v1(1.03,19.91) v1(1.03,17.37) v1(1.03,14.83) v1(1.03,12.29) v1(1.03,9.75) v1(1.03,7.21) v1(1.12,1.03) v1(4.37,61.52) v1(4.37,56.44) v1(4.37,51.36) v1(4.37,46.28) v1(4.37,41.2) v1(4.37,36.12) v1(4.37,31.04) v1(4.37,15.8) v1(6.37,72.97) v1(6.37,1.03) v1(8.91,72.97) v1(8.91,1.03) v1(9.45,66.6) v1(9.45,61.52) v1(9.45,56.44) v1(9.45,51.36) v1(9.45,46.28) v1(9.45,41.2) v1(9.45,36.12) v1(9.45,31.04) v1(9.45,15.8) v1(9.45,10.72) v1(9.45,5.64) v1(11.07,69.81) v1(11.45,72.97) v1(11.45,1.03) v1(13.99,72.97) v1(13.99,1.03) v1(14.53,51.36) v1(14.53,46.28) v1(14.53,41.2) v1(14.53,36.12) v1(14.53,31.04) v1(14.53,25.96) v1(14.53,20.88) v1(14.53,15.8) v1(14.53,10.72) v1(14.53,5.64) v1(16.15,69.81) v1(16.53,72.97) v1(16.53,1.03) v1(17.89,39.1) v1(19.07,72.97) v1(19.07,1.03) v1(21.22,44.87) v1(21.23,69.81) v1(21.61,72.97) v1(21.61,1.03) v1(22.6,63.28) v1(22.6,59.47) v1(23.87,60.74) v1(23.87,56.93) v1(24.15,72.97) v1(24.15,1.03) v1(25.14,63.28) v1(25.14,59.47) v1(26.41,60.74) v1(26.41,56.93) v1(26.69,72.97) v1(26.69,1.03) v1(27.68,63.28) v1(27.68,59.47) v1(28.95,60.74) v1(28.95,56.93) v1(29.23,72.97) v1(29.23,1.03) v1(30.22,63.28) v1(30.22,59.47) v1(30.47,51.82) v1(31.49,60.74) v1(31.49,56.93) v1(31.77,72.97) v1(31.77,1.03) v1(32.72,37.12) v1(32.76,63.28) v1(32.76,59.47) v1(32.96,42.71) v1(34.03,60.74) v1(34.03,56.93) v1(34.31,72.97) v1(34.31,1.03) v1(35.3,63.28) v1(35.3,59.47) v1(36.57,60.74) v1(36.57,56.93) v1(36.85,72.97) v1(36.85,1.03) v1(37.84,59.47) v1(39.11,60.74) v1(39.11,56.93) v1(39.39,72.97) v1(39.39,1.03) v1(40.38,63.28) v1(40.38,59.47) v1(41.65,60.74) v1(41.65,56.93) v1(41.93,72.97) v1(41.93,1.03) v1(42.92,63.28) v1(42.92,59.47) v1(44.19,60.74) v1(44.19,56.93) v1(44.47,72.97) v1(44.47,1.03) v1(45.46,63.28) v1(45.46,59.47) v1(46.73,60.74) v1(46.73,56.93) v1(47.01,72.97) v1(47.01,1.03) v1(48,63.28) v1(48,59.47) v1(49.27,60.74) v1(49.27,56.93) v1(49.55,72.97) v1(49.55,1.03) v1(50.54,63.28) v1(50.54,59.47) v1(51.81,60.74) v1(51.81,56.93) v1(52.09,72.97) v1(52.09,1.03) v1(53.08,63.28) v1(53.08,59.47) v1(54.63,72.97) v1(54.63,1.03) v1(57.17,72.97) v1(57.18,14.07) v1(57.17,1.03) v1(59.71,72.97) v1(59.71,1.03) v1(62.25,72.97) v1(62.25,1.03) v1(62.48,15.36) v1(64.44,70.69) v1(64.79,72.97) v1(64.79,1.03) v1(67.33,72.97) v1(67.33,1.03) v1(68.55,64.54) v1(69.17,30.42) v1(69.52,70.69) v1(69.57,64.54) v1(69.87,72.97) v1(69.87,1.03) v1(70.44,30.42) v1(70.58,64.54) v1(71.81,29.87) v1(72.41,72.97) v1(72.41,1.03) v1(73.01,66.03) v1(73.08,29.87) v1(74.02,66.03) v1(74.35,29.87) v1(74.6,70.69) v1(74.95,72.97) v1(74.95,1.03) v1(75.04,66.03) v1(77.49,72.97) v1(77.49,1.03) v1(80.03,72.97) v1(80.03,1.03) v1(81.32,35.56) v1(82.05,67.42) v1(82.05,66.4) v1(82.05,65.38) v1(82.57,72.97) v1(82.57,1.03) v1(83.06,35.59) v1(83.83,28.54) v1(86.95,72.97) v1(86.97,68.27) v1(86.97,65.73) v1(86.97,63.19) v1(86.97,60.65) v1(86.97,58.11) v1(86.97,55.57) v1(86.97,53.03) v1(86.97,50.49) v1(86.97,47.95) v1(86.97,45.41) v1(86.97,42.87) v1(86.97,40.33) v1(86.97,37.79) v1(86.97,35.25) v1(86.97,32.71) v1(86.97,30.17) v1(86.97,27.63) v1(86.97,25.09) v1(86.97,22.45) v1(86.97,19.91) v1(86.97,17.37) v1(86.97,14.83) v1(86.97,12.29) v1(86.97,9.75) v1(86.97,7.21) v1(86.95,1.03)
P12V: length 16.6
  TOP w0.305: 73.63,36.34 73.63,36.59 73.45,36.78 U1.50 ; 72.6,36.32 72.6,36.66 72.44,36.81 U1.48 ; 74.07,34.93 C34.2 72.25,34.93 ; U1.11 v1(73.45,50)
  TOP w0.508: v1(73.63,35.44) 73.63,36.34 ; v1(72.6,35.44) 72.6,36.32
  BOTTOM w0.305: 71.74,35.12 C32.1 ; C32.1 71.74,33.14 ; C32.1 74.99,35.12 ; C32.1 74.99,33.14
  vias: v1(39.21,46.83) v1(39.21,45.82) v1(39.21,44.8) v1(39.21,43.79) v1(40.38,62.01) v1(41.65,59.47) v1(41.65,58.2)
V5REG: length 7.2
  TOP w0.305: 71.55,36.17 71.94,36.57 U1.47
  TOP w0.508: v1(70.74,33.45) 70.25,33.45 C33.2 69.87,34.86 71.02,36.01 71.39,36.01 71.55,36.17
  BOTTOM w0.508: C31.1 70.25,32.96 v1(70.74,33.45)
V12_SWL-NC: length 4.8
  TOP w0.305: U1.52 74.44,38.67 74.14,38.98 v1(74.11,38.98) 73.94,38.81 U1.51 73.94,37.06 v1(74.22,36.78) 74.44,36.99 U1.52
VCC: length 69.7
  TOP w0.305: C26.1 48.03,11.22 ; C26.1 C25.1 ; C26.1 48.3,10.38 48.38,10.3 ; C26.1 46.78,11.22 ; L1.2 26.3,49.23 ; L1.2 25.46,49.53 25.47,49.54 ; L1.2 25.46,47.61 25.45,47.61 ; L1.2 26.3,47.97 ; C8.1 48.67,34.63 ; C8.1 47.41,34.63 ; C8.1 48.95,35.47 48.96,35.49 ; C8.1 C7.1 ; C7.1 C6.1 ; C7.1 45.51,34.63 ; C7.1 46.76,34.63 ; C6.1 44.86,34.63 ; C6.1 43.6,34.63 ; C6.1 C5.1 ; C3.1 37.6,35.47 37.58,35.46 ; C3.1 37.89,34.63 ; C3.1 39.14,34.63 ; C3.1 C4.1 ; 41.7,34.63 C5.1 ; C5.1 C4.1 ; C5.1 42.95,34.63 ; 42.97,11.22 C24.1 ; C24.1 C25.1 ; C24.1 44.22,11.22 ; C24.1 C23.1 ; C25.1 46.13,11.22 ; C25.1 44.87,11.22 ; 40.79,10.38 40.79,10.38 C23.1 ; 39.79,34.63 C4.1 ; C4.1 41.05,34.63 ; C23.1 42.32,11.22 ; C23.1 41.06,11.22
  TOP w0.381: C9.1 57.69,44.34 v1(57.54,44.49) ; v1(48.04,34.37) C8.1 ; v1(46.14,34.37) C7.1 ; v1(42.33,34.37) C5.1 ; v1(47.41,11.39) C26.1 ; v1(41.69,11.39) C23.1 ; v1(45.5,11.39) C25.1 ; R2.2 v1(26.45,7.69) ; v1(44.23,34.37) C6.1 ; v1(40.42,34.46) C4.1 ; v1(43.6,11.39) C24.1 ; v1(38.52,34.46) C3.1
  BOTTOM w0.381: v1(48.03,14.11) U500.B16 ; v1(45.49,33.16) U500.T14 ; v1(49.3,31.89) U500.R17 ; v1(44.22,14.11) U500.B13 ; v1(45.49,12.84) U500.A14 ; v1(41.68,14.11) U500.B11 ; v1(42.95,14.11) U500.B12 ; v1(42.95,31.89) U500.R12 ; v1(48.03,12.84) U500.A16 ; v1(44.22,31.89) U500.R13 ; v1(48.03,31.89) U500.R16 ; v1(42.95,33.16) U500.T12 ; v1(42.95,12.84) U500.A12 ; v1(48.03,33.16) U500.T16
  vias: v1(26.54,49.06) v1(26.54,48.05) v1(27.55,49.06) v1(27.55,48.05) v1(55.53,48.2) v1(55.53,47.06) v1(55.53,46.04) v1(55.53,44.9)
VCC2: length 72.9
  TOP w0.254: v1(79.16,45.79) U1.73 81.36,45.79 81.47,45.9 82.34,45.9 C29.2 ; v1(79.16,48.29) U1.78 ; U1.38 v1(68.28,40.79) ; U1.33 v1(65.69,43.29) ; U1.28 v1(65.69,45.79) ; U1.49 72.94,38.95 v1(73.13,39.13) ; v1(65.69,48.29) U1.23 ; U1.63 v1(79.16,40.79) ; U1.68 v1(79.16,43.29)
  TOP w0.305: C12.1 21.09,28 ; C12.1 C13.1 ; C12.1 20.25,28.4 20.24,28.41 20.25,28.42 C11.1 ; C12.1 21.09,26.74 ; C11.1 20.25,30.19 20.26,30.2 ; C11.1 21.09,29.9 ; C11.1 21.09,28.65 ; C36.2 78.5,35.41 ; C36.2 78.5,31.44 ; C36.2 77.28,31.44 ; C36.2 77.28,35.41 ; C13.1 21.09,26.09 ; C13.1 21.09,24.84 ; C13.1 20.25,24.39 20.25,24.39 ; C22.1 21.09,14.68 ; C22.1 20.25,14.24 20.23,14.22 ; C22.1 C21.1 ; C22.1 21.09,15.93 ; C21.1 20.25,18.14 20.22,18.17 ; C21.1 21.09,16.58 ; C21.1 21.09,17.84 ; TP28.1 78.43,26.98 ; TP28.1 77.09,28.32 ; TP28.1 78.43,28.32 ; TP28.1 77.09,26.98 ; 76.36,31.43 D3.1 79.22,28.57 ; 76.55,35.37 C35.2 75.29,35.37
  TOP w0.381: v1(65.69,48.29) 65.06,48.29 64.87,48.48 C14.2
  TOP w0.508: C29.2 v1(84.67,44.39)
  TOP w0.762: D3.1 77.89,30.09 C36.2 77.89,33.77 77.12,34.53 C35.2 75.39,34.53 v1(75.37,34.51)
  TOP w1.016: D3.1 77.76,29.96 TP28.1
  02_PWR w0.305: 77.09,26.98 TP28.1 ; TP28.1 78.43,28.32 ; TP28.1 77.09,28.32 ; TP28.1 78.43,26.98
  BOTTOM w0.381: v1(22.89,15.38) U500.C1 ; v1(22.89,16.65) U500.D1 ; v1(22.89,28.08) U500.M1 ; v1(22.89,29.35) U500.N1
  vias: v1(53.63,6.57) v1(53.63,5.42) v1(54.64,6.57) v1(54.64,5.42) v1(55.66,6.57) v1(55.66,5.42) v1(56.68,6.57) v1(56.68,5.42) v1(57.69,6.57) v1(57.69,5.42)
3P3V:
  vias: v1(53.08,62.01) v1(53.08,60.74) v1(63.92,60.82) v1(63.92,59.55) v1(63.92,58.28) v1(65.5,60.81) v1(65.5,59.54) v1(65.5,58.27)
13A:
  vias: v1(37.84,63.28)
13B:
  vias: v1(37.84,62.01)
DAD_ADDR_0: length 38.5
  TOP w0.187: v1(69.34,49.97) 69.34,50.01 69.44,50.12 U1.19
  BOTTOM w0.213: v1(37.84,58.2) 37.84,58.09 37.26,57.51 37.26,55.64 42.73,50.17 69.13,50.17 v1(69.34,49.97)
DAD_ADDR_1: length 42.2
  TOP w0.187: v1(66.96,56.35) 66.71,56.1 66.71,54.83 67.61,53.93 69.11,53.93 69.94,53.09 U1.18
  BOTTOM w0.213: v1(66.96,56.35) 66.2,55.59 45.63,55.59 44.83,56.39 44.83,60.96 44.39,61.39 38.49,61.39 v1(37.84,60.74)
DAD_ADDR_2: length 38.3
  TOP w0.187: U1.17 70.44,50.06 70.38,50 v1(70.33,50)
  BOTTOM w0.213: v1(70.33,50) 70.33,50.41 69.59,51.15 43.42,51.15 38.48,56.09 38.48,57.16 39.11,57.79 v1(39.11,58.2)
DAD_ADDR_3: length 38.1
  TOP w0.187: v1(67.34,55.33) 67.99,54.69 69.5,54.69 70.94,53.24 U1.16
  BOTTOM w0.213: v1(39.11,59.47) 39.54,59.47 40.21,58.8 43.31,58.8 43.6,58.51 43.6,56.35 45.12,54.83 66.84,54.83 v1(67.34,55.33)
DAD_IRQZ: length 54.4
  TOP w0.187: U1.43 v1(69.94,36.66)
  BOTTOM w0.213: v1(69.94,36.66) 67.99,38.62 65.11,38.62 64.02,37.53 TP22.1 56.65,40.45 56.65,42.6 50.33,48.92 41.49,48.92 35.9,54.51 35.9,58.59 36.14,58.83 38.03,58.83 38.49,59.3 38.49,59.67 38.95,60.13 39.77,60.13 v1(40.38,60.74)
DAD_MODE_0: length 40.2
  TOP w0.187: U1.3 77.44,52.37 v1(77.32,52.5)
  BOTTOM w0.213: v1(77.32,52.5) 77.32,52.7 76.82,53.2 44.11,53.2 v1(40.38,56.93)
DAD_MODE_1: length 43.5
  TOP w0.187: v1(78.77,53.8) 77.94,52.97 U1.2
  BOTTOM w0.213: v1(40.38,58.2) 40.99,57.59 41.94,57.59 42.28,57.24 42.28,56.51 44.73,54.06 78.51,54.06 v1(78.77,53.8)
DAD_OEZ: length 82.9
  TOP w0.187: U1.6 v1(75.94,50.05)
  04_SIG1 w0.135: v1(75.94,50.05) 77.47,51.58 79.16,51.58 84.18,56.6 84.18,65.05 TP24.1
  BOTTOM w0.213: v1(75.94,50.05) 76.78,50.89 79.61,50.89 81.74,53.01 81.74,54.86 68.98,67.61 43.83,67.61 39.71,63.49 39.71,63.06 39.33,62.68 37.17,62.68 v1(36.57,63.28)
DAD_SEL_0: length 57.3
  TOP w0.187: U1.5 v1(76.44,52.6)
  BOTTOM w0.213: v1(39.11,62.01) 39.57,62.01 40.22,62.66 48.41,62.66 48.64,62.9 48.64,63.94 51.38,66.67 65.4,66.67 69.19,62.88 72.24,62.88 80.92,54.2 80.92,53.36 79.38,51.81 76.98,51.81 76.44,52.35 v1(76.44,52.6)
DAD_SEL_1: length 62.9
  TOP w0.187: U1.4 v1(76.95,50.07)
  BOTTOM w0.213: v1(76.95,50.07) 79.95,50.07 82.48,52.6 82.48,56.76 79.81,59.43 78.71,59.43 69.48,68.66 43.64,68.66 39.11,64.14 v1(39.11,63.28)
DAD_STRB: length 60.3
  TOP w0.187: v1(71.34,50) 71.38,50 71.44,50.06 U1.15
  04_SIG1 w0.135: v1(71.34,50) 75.73,54.38 TP23.1
  BOTTOM w0.213: v1(71.34,50) 71.34,50.63 70.02,51.95 43.98,51.95 39.73,56.21 39.73,58.5 39.39,58.83 38.88,58.83 38.54,58.49 38.54,58.04 37.84,57.34 v1(37.84,56.93)
DAD_VBIAS_SWL: length 16.6
  TOP w0.305: U1.8 74.94,52.21 74.77,52.38 74.77,53.1 75.29,53.62 77.39,53.62 78.61,54.84
  TOP w0.762: 78.61,54.84 80.38,56.6 D2.2 81.9,57.61 81.65,57.85 81.65,60.28 80.9,61.03 L4.2
DCLKAN: length 111.8
  06_SIG2 w0.094: v1(27.68,58.2) 27.68,57.8 27.79,57.69 28,57.69 28.19,57.89 28.19,66.18 29.78,67.77 60.14,67.77 61.98,65.93 61.98,58.14 58.92,55.09 58.92,47.73 60.49,46.17 60.49,42.06 60.16,41.73 59.46,41.73 59.15,42.04 59.15,45.62 58.91,45.86 58.62,45.86 58.38,45.61 58.38,41.53 60.87,39.04 60.87,24.5 53.53,17.16 52.35,17.16 v1(51.84,16.65)
  BOTTOM w0.213: v1(51.84,16.65) U500.D19
DCLKAP: length 111.8
  06_SIG2 w0.094: v1(27.68,56.93) 27.68,57.33 27.79,57.44 28.1,57.44 28.45,57.78 28.45,66.07 29.89,67.51 60.03,67.51 61.73,65.82 61.73,58.25 58.67,55.19 58.67,47.63 60.23,46.07 60.23,42.16 60.05,41.99 59.56,41.99 59.4,42.14 59.4,45.73 59.02,46.11 58.52,46.11 58.12,45.71 58.12,41.43 60.62,38.93 60.62,24.61 53.42,17.41 52.18,17.41 52.08,17.31 51.72,17.31 51.57,17.46 51.57,17.81 51.68,17.92 v1(51.84,17.92)
  BOTTOM w0.213: U500.E19 v1(51.84,17.92)
DCLKBN: length 61.9
  06_SIG2 w0.094: v1(48,58.2) 48,57.8 47.89,57.69 46.38,57.69 45.97,57.28 45.97,49.11 43.08,46.22 43.08,40.35 42.82,40.09 42.22,40.09 41.94,40.37 41.94,47.3 41.48,47.76 40.53,47.76 40.04,47.26 40.04,39.6 40.87,38.76 49.97,38.76 52.35,36.38 52.35,29.05 52.15,28.84 51.95,28.84 51.84,28.95 v1(51.84,29.35)
  BOTTOM w0.213: v1(51.84,29.35) U500.N19
DCLKBP: length 61.9
  06_SIG2 w0.094: v1(51.84,28.08) 51.84,28.48 51.95,28.59 52.25,28.59 52.61,28.94 52.61,36.49 50.08,39.02 40.98,39.02 40.29,39.7 40.29,47.16 40.64,47.5 41.37,47.5 41.68,47.19 41.68,40.26 42.11,39.83 42.92,39.83 43.34,40.25 43.34,46.11 46.22,49 46.22,57.18 46.48,57.44 47.89,57.44 48,57.33 v1(48,56.93)
  BOTTOM w0.213: U500.M19 v1(51.84,28.08)
DDAN1: length 111.8
  04_SIG1 w0.094: v1(32.76,58.2) 33.03,57.93 33.03,57.68 32.85,57.5 32.56,57.5 32.26,57.8 32.26,63.52 32.57,63.83 50.49,63.83 50.84,64.18 50.84,64.76 50.51,65.09 38.24,65.09 38.01,65.31 38.01,65.62 38.27,65.87 51.34,65.87 51.73,65.49 51.73,64.26 52.15,63.83 58.11,63.83 60.24,61.7 60.24,59.11 57.04,55.91 57.04,50.06 58.06,49.04 58.06,44.1 56.74,42.78 56.74,34.45 55.99,33.7 55.99,30.23 54.01,28.24 54.01,24.04 53.59,23.62 53.04,23.62 52.39,22.97 52.39,21.37 53.11,20.65 v1(53.11,20.46)
  BOTTOM w0.213: v1(53.11,20.46) U500.G20
DDAN3: length 111.8
  04_SIG1 w0.094: v1(51.84,21.73) 51.62,21.73 51.53,21.64 51.53,21.12 51.64,21.02 52.03,21.02 52.38,20.66 52.38,20.05 52.48,19.95 53.43,19.95 54.27,20.8 54.27,22.5 55.13,23.36 55.13,27.58 57.38,29.83 57.38,33.08 58.28,33.97 58.28,42.44 59.19,43.35 59.19,49.65 58.36,50.47 58.36,55.65 61.08,58.36 61.08,65.36 59.63,66.8 54.2,66.8 54.02,66.63 54.02,66.01 54.11,65.92 57.79,65.92 58.13,65.58 58.13,64.91 57.83,64.61 53.06,64.61 52.63,65.04 52.63,66.33 52.14,66.83 32.89,66.83 32.65,66.59 32.65,66.19 32.83,66.01 36.27,66.01 36.59,65.69 36.59,65.05 36.23,64.69 31.56,64.69 30.98,64.11 30.98,59.07 31.12,58.94 31.42,58.94 31.55,59.07 31.55,59.41 v1(31.49,59.47)
  BOTTOM w0.213: U500.H19 v1(51.84,21.73)
DDAN5: length 111.8
  04_SIG1 w0.094: v1(50.57,19.19) 50.98,19.19 51.08,19.29 51.08,19.64 50.97,19.75 49.94,19.75 49.74,19.55 49.74,17.69 50.02,17.41 53.82,17.41 56.49,20.08 56.49,27.36 60.4,31.28 60.4,50.38 59.55,51.23 59.55,55.16 62.19,57.79 62.19,63.78 62.52,64.1 63.04,64.1 63.45,63.69 63.45,62.46 63.61,62.31 64.05,62.31 64.2,62.46 64.2,63.99 60.24,67.95 32.4,67.95 29.71,65.27 29.71,57.8 30.07,57.44 30.44,57.44 30.62,57.61 30.62,58.04 30.46,58.2 v1(30.22,58.2)
  BOTTOM w0.213: v1(50.57,19.19) U500.F18
DDAN7: length 111.8
  06_SIG2 w0.094: v1(50.57,17.92) 50.63,17.86 50.63,17.6 50.49,17.45 50.11,17.45 49.82,17.74 49.82,21.94 50.63,22.75 55.11,22.75 57.25,24.89 57.25,37.79 52.51,42.53 52.51,53.87 52.73,54.09 53.26,54.09 53.43,53.92 53.43,43.89 53.82,43.5 54.42,43.5 54.79,43.87 54.79,57.18 54.08,57.89 54.08,64.9 53.34,65.64 43.99,65.64 43.43,65.08 43.43,63.03 43.17,62.77 31.18,62.77 30.73,62.33 30.73,59.26 30.44,58.96 29.06,58.96 28.95,59.07 v1(28.95,59.47)
  BOTTOM w0.213: U500.E18 v1(50.57,17.92)
DDAN9: length 111.8
  04_SIG1 w0.094: v1(26.41,59.47) 26.41,59.04 26.57,58.88 26.73,58.88 26.92,59.07 26.92,64.79 31.45,69.32 60.81,69.32 65.66,64.47 65.66,61.95 64.78,61.07 64.78,57.94 61.14,54.31 61.14,52.21 61.35,51.99 61.76,51.99 61.97,52.21 61.97,53.82 62.35,54.2 62.98,54.2 63.31,53.87 63.31,48.24 61.77,46.71 61.77,30.68 57.89,26.79 57.89,19.54 54.13,15.79 53.52,15.79 v1(53.11,15.38)
  BOTTOM w0.213: v1(53.11,15.38) U500.C20
DDAN11: length 111.8
  06_SIG2 w0.094: v1(25.14,58.2) 25.69,58.2 25.85,58.04 25.85,57.66 25.72,57.53 24.92,57.53 24.63,57.82 24.63,63.91 29.35,68.63 60.76,68.63 62.98,66.42 62.98,57.26 60.03,54.31 60.03,47.87 61.73,46.17 61.73,23.25 53.35,14.87 51.36,14.87 51.07,14.58 51.07,13.9 50.81,13.64 50.67,13.64 50.57,13.74 v1(50.57,14.11)
  BOTTOM w0.213: U500.B18 v1(50.57,14.11)
DDAN13: length 111.8
  04_SIG1 w0.094: v1(53.11,12.84) 53.55,13.27 53.64,13.27 59.17,18.8 59.17,26.5 63.1,30.43 63.1,45.69 64.54,47.13 64.54,55.34 66.78,57.58 66.78,64.93 61.28,70.43 30.97,70.43 24.38,63.84 24.38,59.21 24.13,58.96 23.98,58.96 23.87,59.07 v1(23.87,59.47)
  BOTTOM w0.213: v1(53.11,12.84) U500.A20
DDAN15: length 111.8
  06_SIG2 w0.094: v1(22.6,62.01) 23.24,62.01 23.38,61.86 23.38,61.42 23.22,61.25 22.45,61.25 22.08,61.62 22.08,63.51 28.54,69.97 61.02,69.97 64.5,66.48 64.5,54.51 63.03,53.04 63.03,22.97 53.66,13.6 51.93,13.6 51.84,13.69 v1(51.84,14.11)
  BOTTOM w0.213: U500.B19 v1(51.84,14.11)
DDAP1: length 111.8
  04_SIG1 w0.094: v1(32.76,56.93) 32.76,56.93 32,57.69 32,63.63 32.46,64.08 50.38,64.08 50.59,64.29 50.59,64.65 50.41,64.84 38.13,64.84 37.76,65.21 37.76,65.72 38.16,66.13 51.45,66.13 51.98,65.59 51.98,64.36 52.26,64.08 58.22,64.08 60.49,61.81 60.49,59.01 57.29,55.81 57.29,50.17 58.31,49.15 58.31,44 57,42.68 57,34.35 56.25,33.6 56.25,30.12 54.26,28.14 54.26,23.93 53.7,23.37 53.15,23.37 52.65,22.87 52.65,21.47 52.82,21.3 53.01,21.3 53.11,21.4 v1(53.11,21.73)
  BOTTOM w0.213: U500.H20 v1(53.11,21.73)
DDAP3: length 111.8
  04_SIG1 w0.094: v1(51.84,20.46) 51.84,20.17 52.32,19.7 53.53,19.7 54.53,20.69 54.53,22.4 55.38,23.25 55.38,27.47 57.64,29.73 57.64,32.97 58.53,33.87 58.53,42.33 59.44,43.25 59.44,49.75 58.62,50.58 58.62,55.54 61.33,58.26 61.33,65.47 59.74,67.06 54.09,67.06 53.77,66.73 53.77,65.91 54.01,65.67 57.68,65.67 57.88,65.47 57.88,65.02 57.72,64.86 53.17,64.86 52.89,65.14 52.89,66.44 52.24,67.08 32.78,67.08 32.4,66.7 32.4,66.08 32.72,65.76 36.16,65.76 36.34,65.58 36.34,65.15 36.13,64.94 31.46,64.94 30.73,64.22 30.73,58.97 31.01,58.68 31.34,58.68 31.49,58.54 v1(31.49,58.2)
  BOTTOM w0.213: v1(51.84,20.46) U500.G19
DDAP5: length 111.8
  04_SIG1 w0.094: v1(50.57,20.46) 50.57,20.45 50.12,20 49.84,20 49.49,19.66 49.49,17.58 49.91,17.16 53.93,17.16 56.74,19.97 56.74,27.26 60.66,31.17 60.66,50.49 59.81,51.34 59.81,55.05 62.45,57.69 62.45,63.67 62.63,63.85 62.93,63.85 63.2,63.58 63.2,62.36 63.5,62.06 64.15,62.06 64.45,62.35 64.45,64.09 60.34,68.2 32.29,68.2 29.46,65.37 29.46,57.69 v1(30.22,56.93)
  BOTTOM w0.213: U500.G18 v1(50.57,20.46)
DDAP7: length 111.8
  06_SIG2 w0.094: v1(28.95,58.2) 28.95,58.6 29.06,58.71 30.54,58.71 30.98,59.15 30.98,62.22 31.28,62.52 43.28,62.52 43.69,62.93 43.69,64.97 44.09,65.38 53.23,65.38 53.82,64.79 53.82,57.78 54.53,57.07 54.53,43.97 54.32,43.75 53.93,43.75 53.69,43.99 53.69,54.02 53.37,54.35 52.63,54.35 52.26,53.98 52.26,42.42 56.99,37.68 56.99,24.99 55.01,23.01 50.52,23.01 49.56,22.05 49.56,17.64 50,17.2 50.46,17.2 50.57,17.08 v1(50.57,16.65)
  BOTTOM w0.213: v1(50.57,16.65) U500.D18
DDAP9: length 111.8
  04_SIG1 w0.094: v1(26.41,58.2) 27.17,58.96 27.17,64.68 31.55,69.06 60.71,69.06 65.41,64.37 65.41,62.06 64.52,61.17 64.52,58.05 60.89,54.41 60.89,52.1 61.25,51.74 61.86,51.74 62.22,52.1 62.22,53.72 62.46,53.95 62.87,53.95 63.05,53.77 63.05,48.35 61.52,46.81 61.52,30.78 57.63,26.9 57.63,19.65 54.02,16.04 53.41,16.04 53.28,16.17 52.76,16.17 52.66,16.28 52.66,16.54 52.76,16.65 v1(53.11,16.65)
  BOTTOM w0.213: U500.D20 v1(53.11,16.65)
DDAP11: length 111.8
  06_SIG2 w0.094: v1(25.14,56.93) 25.14,56.95 24.38,57.71 24.38,64.01 29.25,68.88 60.87,68.88 63.23,66.52 63.23,57.15 60.29,54.21 60.29,47.98 61.99,46.28 61.99,23.15 53.46,14.62 51.47,14.62 51.32,14.47 51.32,13.79 50.92,13.39 50.68,13.39 50.57,13.28 v1(50.57,12.84)
  BOTTOM w0.213: v1(50.57,12.84) U500.A18
DDAP13: length 111.8
  04_SIG1 w0.094: v1(53.11,14.11) 52.78,13.78 52.78,13.63 52.88,13.53 53.54,13.53 58.91,18.9 58.91,26.61 62.84,30.54 62.84,45.79 64.28,47.23 64.28,55.45 66.52,57.69 66.52,64.82 61.17,70.17 31.08,70.17 24.64,63.73 24.64,59.11 24.24,58.71 23.98,58.71 23.85,58.58 23.85,58.22 v1(23.87,58.2)
  BOTTOM w0.213: U500.B20 v1(53.11,14.11)
DDAP15: length 111.8
  06_SIG2 w0.094: v1(22.6,60.74) 22.39,60.95 21.82,61.52 21.82,63.61 28.43,70.22 61.12,70.22 64.76,66.59 64.76,54.4 63.29,52.93 63.29,22.87 53.77,13.35 51.79,13.35 51.62,13.18 51.62,12.93 51.71,12.84 v1(51.84,12.84)
  BOTTOM w0.213: v1(51.84,12.84) U500.A19
DDBN1: length 61.9
  04_SIG1 w0.094: v1(42.92,58.2) 42.92,57.86 43.03,57.76 43.43,57.76 43.68,57.51 43.68,47.22 43.32,46.87 42.4,46.87 42.08,47.18 42.08,54.06 41.84,54.29 41.47,54.29 41.22,54.04 41.22,36.9 42.08,36.04 46.62,36.04 47.52,35.13 47.52,31.18 47.84,30.86 49.41,30.86 49.92,30.35 49.92,25.39 50.27,25.03 53,25.03 53.21,25.24 53.21,25.44 v1(53.11,25.54)
  BOTTOM w0.213: v1(53.11,25.54) U500.K20
DDBN3: length 62
  06_SIG2 w0.094: v1(51.84,24.27) 51.84,24.63 51.69,24.78 49.94,24.78 49.52,25.2 49.52,27.04 49.81,27.33 49.81,33.8 48.36,35.25 38.54,35.25 37,36.8 37,55.46 37.87,56.34 41.55,56.34 42.29,55.59 42.29,53 42.55,52.74 43.16,52.74 43.43,53.01 43.43,58.71 v1(44.19,59.47)
  BOTTOM w0.213: U500.J19 v1(51.84,24.27)
DDBN5: length 62
  06_SIG2 w0.094: v1(50.57,26.81) 50.57,26.36 50.68,26.25 50.94,26.25 51.08,26.4 51.08,34.55 49.17,36.46 39.71,36.46 39.12,37.05 39.12,38.76 38.16,39.72 38.16,54.87 38.76,55.47 40.26,55.47 40.85,54.88 40.85,50.12 41.28,49.68 44.23,49.68 44.71,50.16 44.71,57.36 45.05,57.7 45.22,57.7 45.46,57.94 v1(45.46,58.2)
  BOTTOM w0.213: v1(50.57,26.81) U500.L18
DDBN7: length 62
  04_SIG1 w0.094: v1(50.57,28.08) 50.57,28.43 50.73,28.59 51.04,28.59 51.33,28.88 51.33,31.08 51.03,31.38 50.24,31.38 50.06,31.56 50.06,33.67 49.14,34.59 49.14,38.32 48.24,39.23 43.11,39.23 42.76,39.57 42.76,44.54 44.84,46.62 44.84,55.61 45.04,55.8 45.75,55.8 45.89,55.67 45.89,46.83 46.32,46.4 47.1,46.4 47.49,46.79 47.49,58.64 47.17,58.96 46.84,58.96 46.73,59.07 v1(46.73,59.47)
  BOTTOM w0.213: U500.M18 v1(50.57,28.08)
DDBN9: length 62
  04_SIG1 w0.094: v1(53.11,30.62) 52.71,30.62 52.59,30.49 52.59,30.24 52.74,30.09 53.74,30.09 54.13,30.48 54.13,33.73 52.53,35.33 52.53,40.34 52.87,40.68 53.51,40.68 53.88,40.31 53.88,35.99 54.08,35.79 54.43,35.79 54.61,35.96 54.61,40.75 53.69,41.66 53.69,46.83 54.07,47.21 54.67,47.21 54.95,46.93 54.95,44.16 55.28,43.83 56.16,43.83 56.46,44.13 56.46,48.37 55.86,48.97 55.86,56.47 53.73,58.59 53.73,59.7 53.46,59.98 49.01,59.98 48.77,59.73 48.77,59.06 49.03,58.8 49.17,58.8 49.27,58.9 v1(49.27,59.47)
  BOTTOM w0.213: v1(53.11,30.62) U500.P20
DDBN11: length 62
  04_SIG1 w0.094: v1(50.54,58.2) 50.54,57.8 50.65,57.69 51.04,57.69 51.29,57.44 51.29,50.14 50.93,49.78 50.03,49.78 49.64,50.16 49.64,55.78 49.35,56.07 49.01,56.07 48.69,55.75 48.69,45.63 48.03,44.97 44.83,44.97 44.52,44.66 44.52,44 44.77,43.75 49.06,43.75 49.51,43.31 49.51,42.39 49.06,41.94 44.22,41.94 43.91,41.64 43.91,40.67 44.12,40.45 49.09,40.45 50.44,39.1 50.44,34.75 51.3,33.89 51.3,32.67 51.03,32.4 50.66,32.4 50.57,32.31 v1(50.57,31.89)
  BOTTOM w0.213: U500.R18 v1(50.57,31.89)
DDBN13: length 61.9
  06_SIG2 w0.094: v1(53.11,33.16) 53.11,32.76 53.22,32.65 53.44,32.65 53.76,32.96 53.76,36.78 50.66,39.88 44.67,39.88 44.22,40.33 44.22,45.47 44.59,45.84 45.18,45.84 45.51,45.51 45.51,41.32 45.67,41.15 46.16,41.15 46.32,41.31 46.32,45.44 46.65,45.78 47.22,45.78 47.56,45.44 47.56,41.36 47.76,41.16 48.14,41.16 48.3,41.33 48.3,45.9 47.1,47.11 47.1,55.38 47.72,56.01 50.77,56.01 51.05,56.3 51.05,58.57 51.44,58.96 51.7,58.96 51.81,59.07 v1(51.81,59.47)
  BOTTOM w0.213: v1(53.11,33.16) U500.T20
DDBN15: length 62
  04_SIG1 w0.094: v1(53.08,58.2) 53.08,57.87 53.22,57.73 53.68,57.73 54.47,56.95 54.47,48.84 52.83,47.2 52.83,41.8 52.46,41.43 51.78,41.43 51.4,41.81 51.4,47.62 53.18,49.41 53.18,55.71 53.01,55.89 52.59,55.89 52.43,55.72 52.43,49.69 50.66,47.92 50.66,40.5 51.62,39.54 51.62,35.16 52.6,34.18 52.6,32.74 52.25,32.39 51.95,32.39 51.84,32.29 v1(51.84,31.89)
  BOTTOM w0.213: U500.R19 v1(51.84,31.89)
DDBP1: length 62
  04_SIG1 w0.094: v1(42.92,56.93) 42.92,57.4 43.02,57.5 43.32,57.5 43.42,57.4 43.42,47.33 43.22,47.12 42.5,47.12 42.34,47.29 42.34,54.16 41.95,54.55 41.37,54.55 40.96,54.14 40.96,36.79 41.97,35.78 46.51,35.78 47.27,35.02 47.27,31.07 47.73,30.61 49.3,30.61 49.67,30.24 49.67,25.28 50.17,24.78 52.93,24.78 53.11,24.6 v1(53.11,24.27)
  BOTTOM w0.213: U500.J20 v1(53.11,24.27)
DDBP3: length 61.9
  06_SIG2 w0.094: v1(44.19,58.2) 44.28,58.2 44.4,58.32 44.4,58.77 44.26,58.91 43.99,58.91 43.69,58.61 43.69,52.9 43.27,52.49 42.45,52.49 42.04,52.89 42.04,55.49 41.44,56.08 37.98,56.08 37.25,55.36 37.25,36.91 38.65,35.51 48.46,35.51 50.07,33.91 50.07,27.23 49.77,26.93 49.77,25.31 50.04,25.03 51.65,25.03 51.84,25.23 v1(51.84,25.54)
  BOTTOM w0.213: v1(51.84,25.54) U500.K19
DDBP5: length 61.9
  06_SIG2 w0.094: v1(50.57,25.54) 50.57,25.86 50.71,26 51.04,26 51.33,26.29 51.33,34.65 49.28,36.71 39.82,36.71 39.37,37.16 39.37,38.87 38.42,39.82 38.42,54.77 38.86,55.21 40.15,55.21 40.59,54.77 40.59,50.01 41.18,49.43 44.34,49.43 44.96,50.05 44.96,57.25 45.16,57.45 45.36,57.45 45.46,57.35 v1(45.46,56.93)
  BOTTOM w0.213: U500.K18 v1(50.57,25.54)
DDBP7: length 61.9
  04_SIG1 w0.094: v1(50.57,29.35) 50.57,28.98 50.71,28.84 50.94,28.84 51.08,28.99 51.08,30.97 50.93,31.13 50.14,31.13 49.81,31.45 49.81,33.57 48.89,34.48 48.89,38.21 48.13,38.97 43,38.97 42.51,39.47 42.51,44.65 44.59,46.73 44.59,55.71 44.93,56.05 45.86,56.05 46.14,55.77 46.14,46.94 46.43,46.65 46.99,46.65 47.24,46.9 47.24,58.54 47.07,58.71 46.42,58.71 46.28,58.56 46.28,58.31 46.39,58.2 v1(46.73,58.2)
  BOTTOM w0.213: v1(50.57,29.35) U500.N18
DDBP9: length 62
  04_SIG1 w0.094: v1(49.27,58.2) 48.51,58.96 48.51,59.83 48.91,60.23 53.56,60.23 53.99,59.81 53.99,58.7 56.11,56.57 56.11,49.08 56.71,48.48 56.71,44.02 56.27,43.57 55.17,43.57 54.69,44.05 54.69,46.82 54.57,46.95 54.17,46.95 53.95,46.73 53.95,41.77 54.86,40.86 54.86,35.86 54.54,35.54 53.97,35.54 53.62,35.88 53.62,40.21 53.41,40.43 52.98,40.43 52.78,40.23 52.78,35.43 54.38,33.83 54.38,30.38 53.84,29.83 53.6,29.83 v1(53.11,29.35)
  BOTTOM w0.213: U500.N20 v1(53.11,29.35)
DDBP11: length 61.9
  04_SIG1 w0.094: v1(50.54,56.93) 50.2,56.93 50.09,57.04 50.09,57.33 50.2,57.44 50.93,57.44 51.04,57.33 51.04,50.25 50.82,50.03 50.13,50.03 49.89,50.27 49.89,55.89 49.46,56.32 48.91,56.32 48.44,55.85 48.44,45.74 47.92,45.22 44.73,45.22 44.27,44.77 44.27,43.89 44.66,43.49 48.96,43.49 49.25,43.2 49.25,42.5 48.95,42.2 44.11,42.2 43.66,41.74 43.66,40.56 44.02,40.2 48.99,40.2 50.19,39 50.19,34.64 51.05,33.78 51.05,32.78 50.92,32.65 50.66,32.65 50.57,32.74 v1(50.57,33.16)
  BOTTOM w0.213: v1(50.57,33.16) U500.T18
